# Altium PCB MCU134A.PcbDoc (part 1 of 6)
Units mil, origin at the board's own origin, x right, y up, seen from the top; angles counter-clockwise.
Board outline 4163.98 x 2693.8 mil, 6 copper layers (Top Layer, GND1, SIG1, PWR, GND2, Bottom), stack 58.132 mil thick; 218 components, 287 nets, 1260 pads, 770 vias.
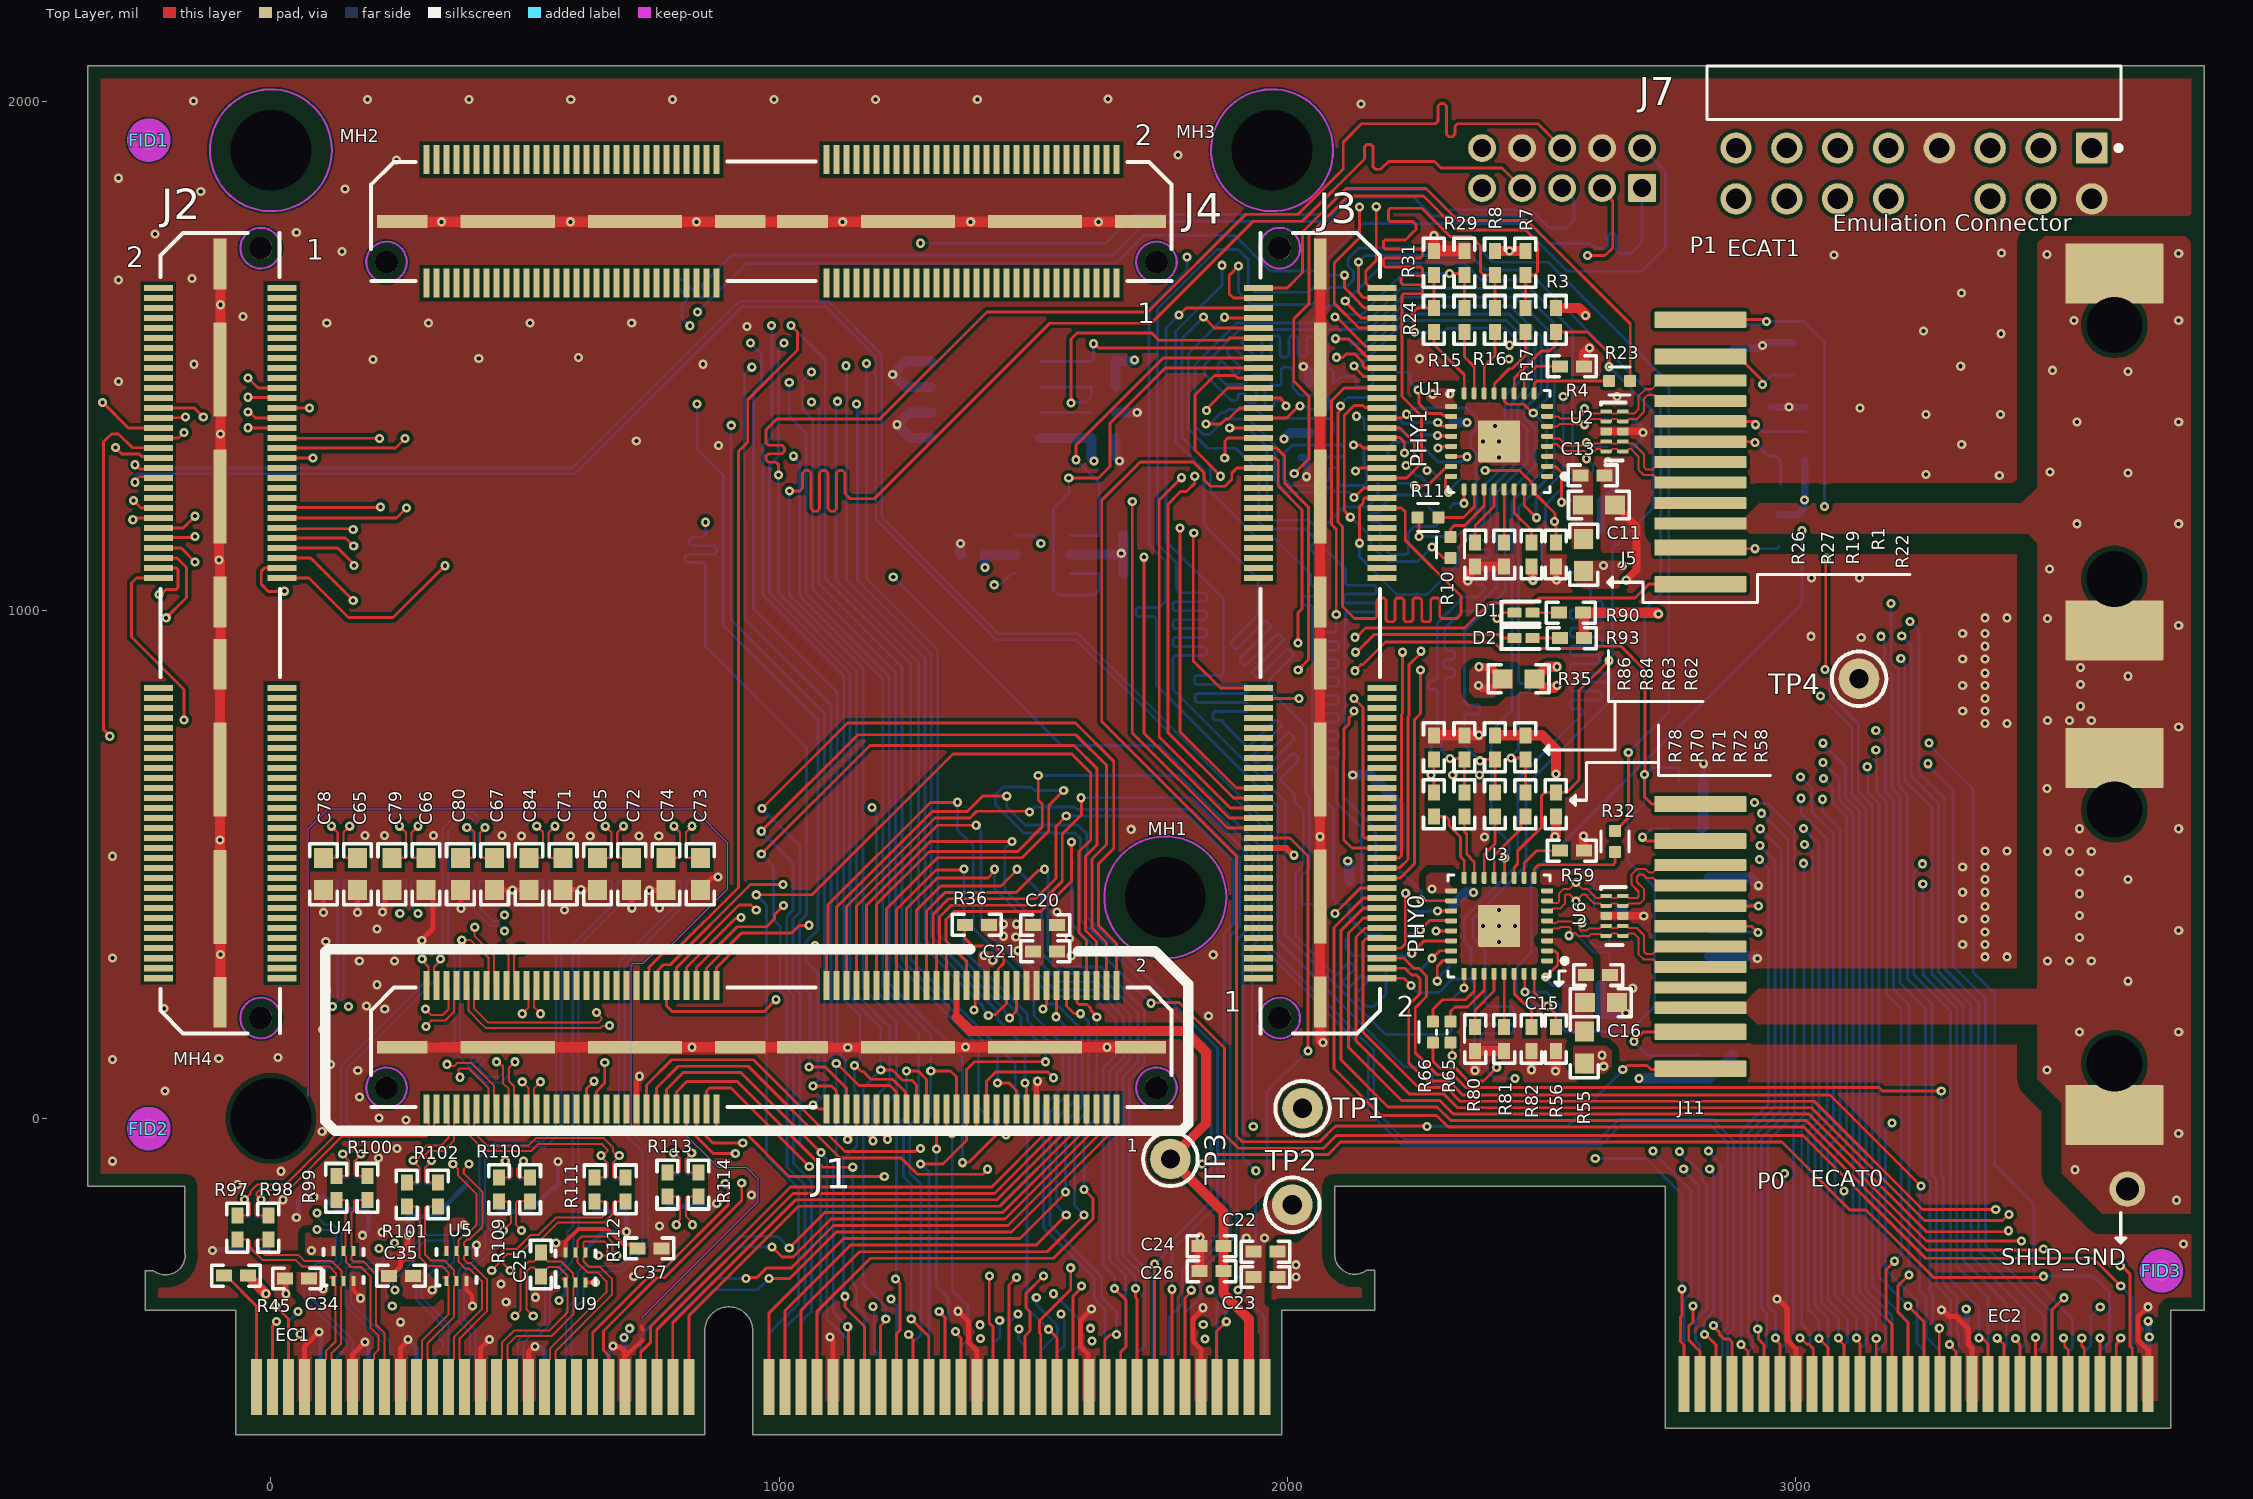
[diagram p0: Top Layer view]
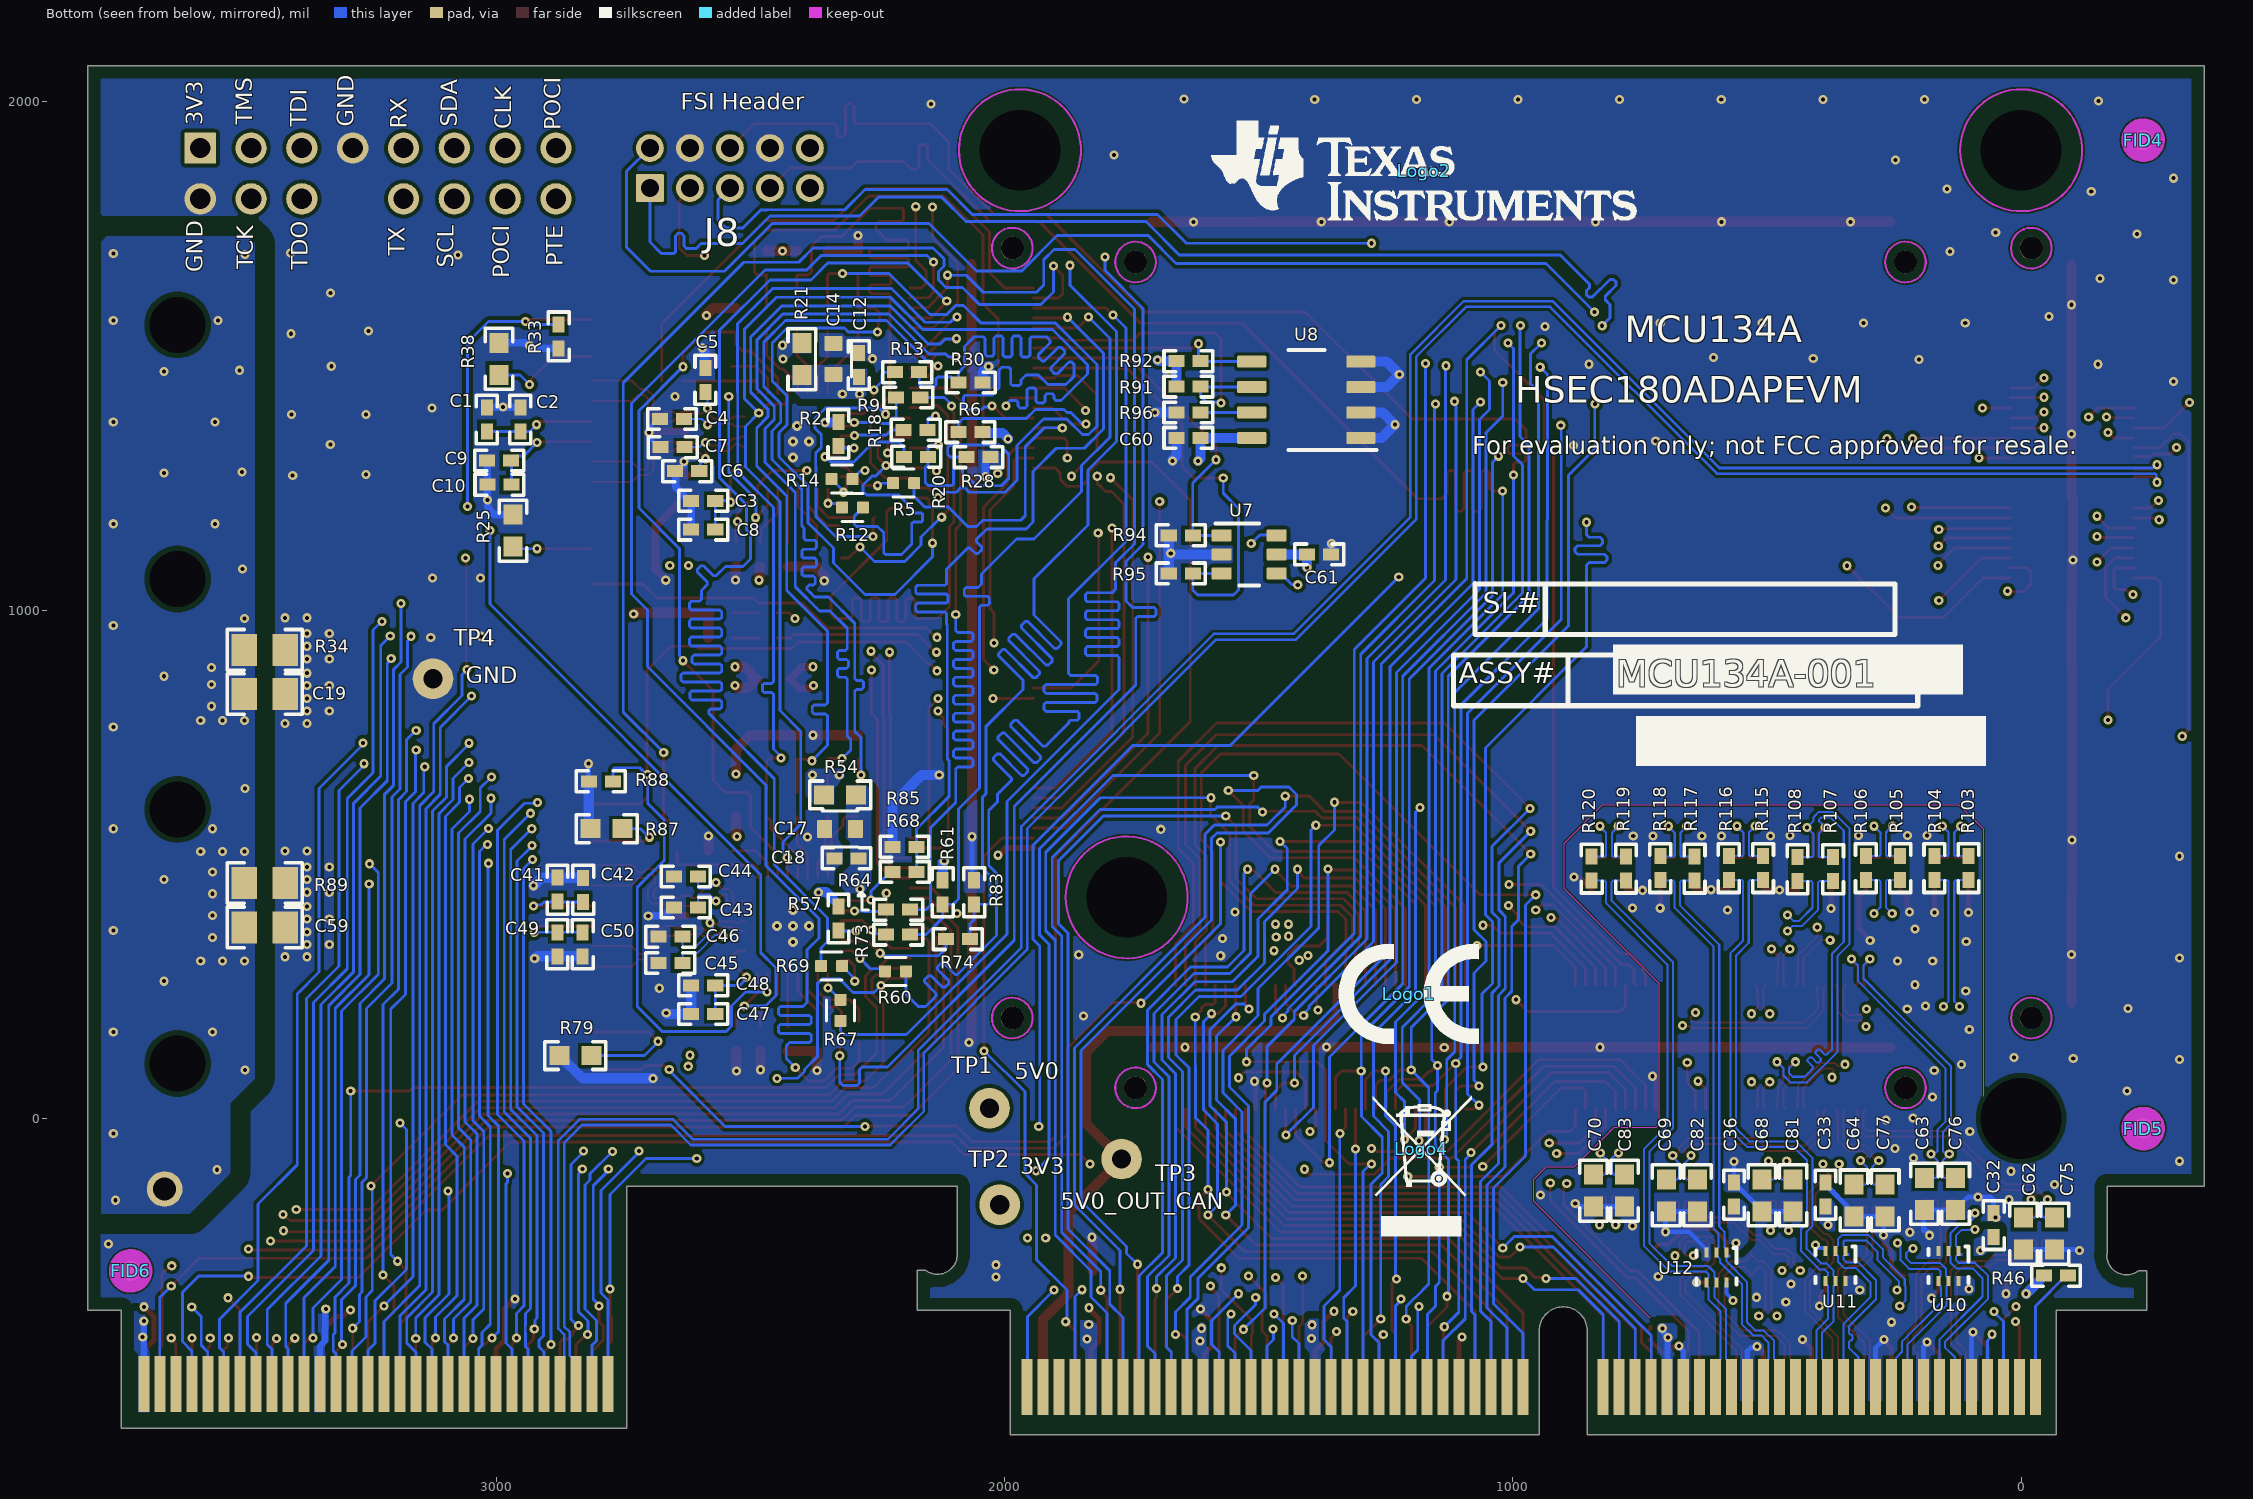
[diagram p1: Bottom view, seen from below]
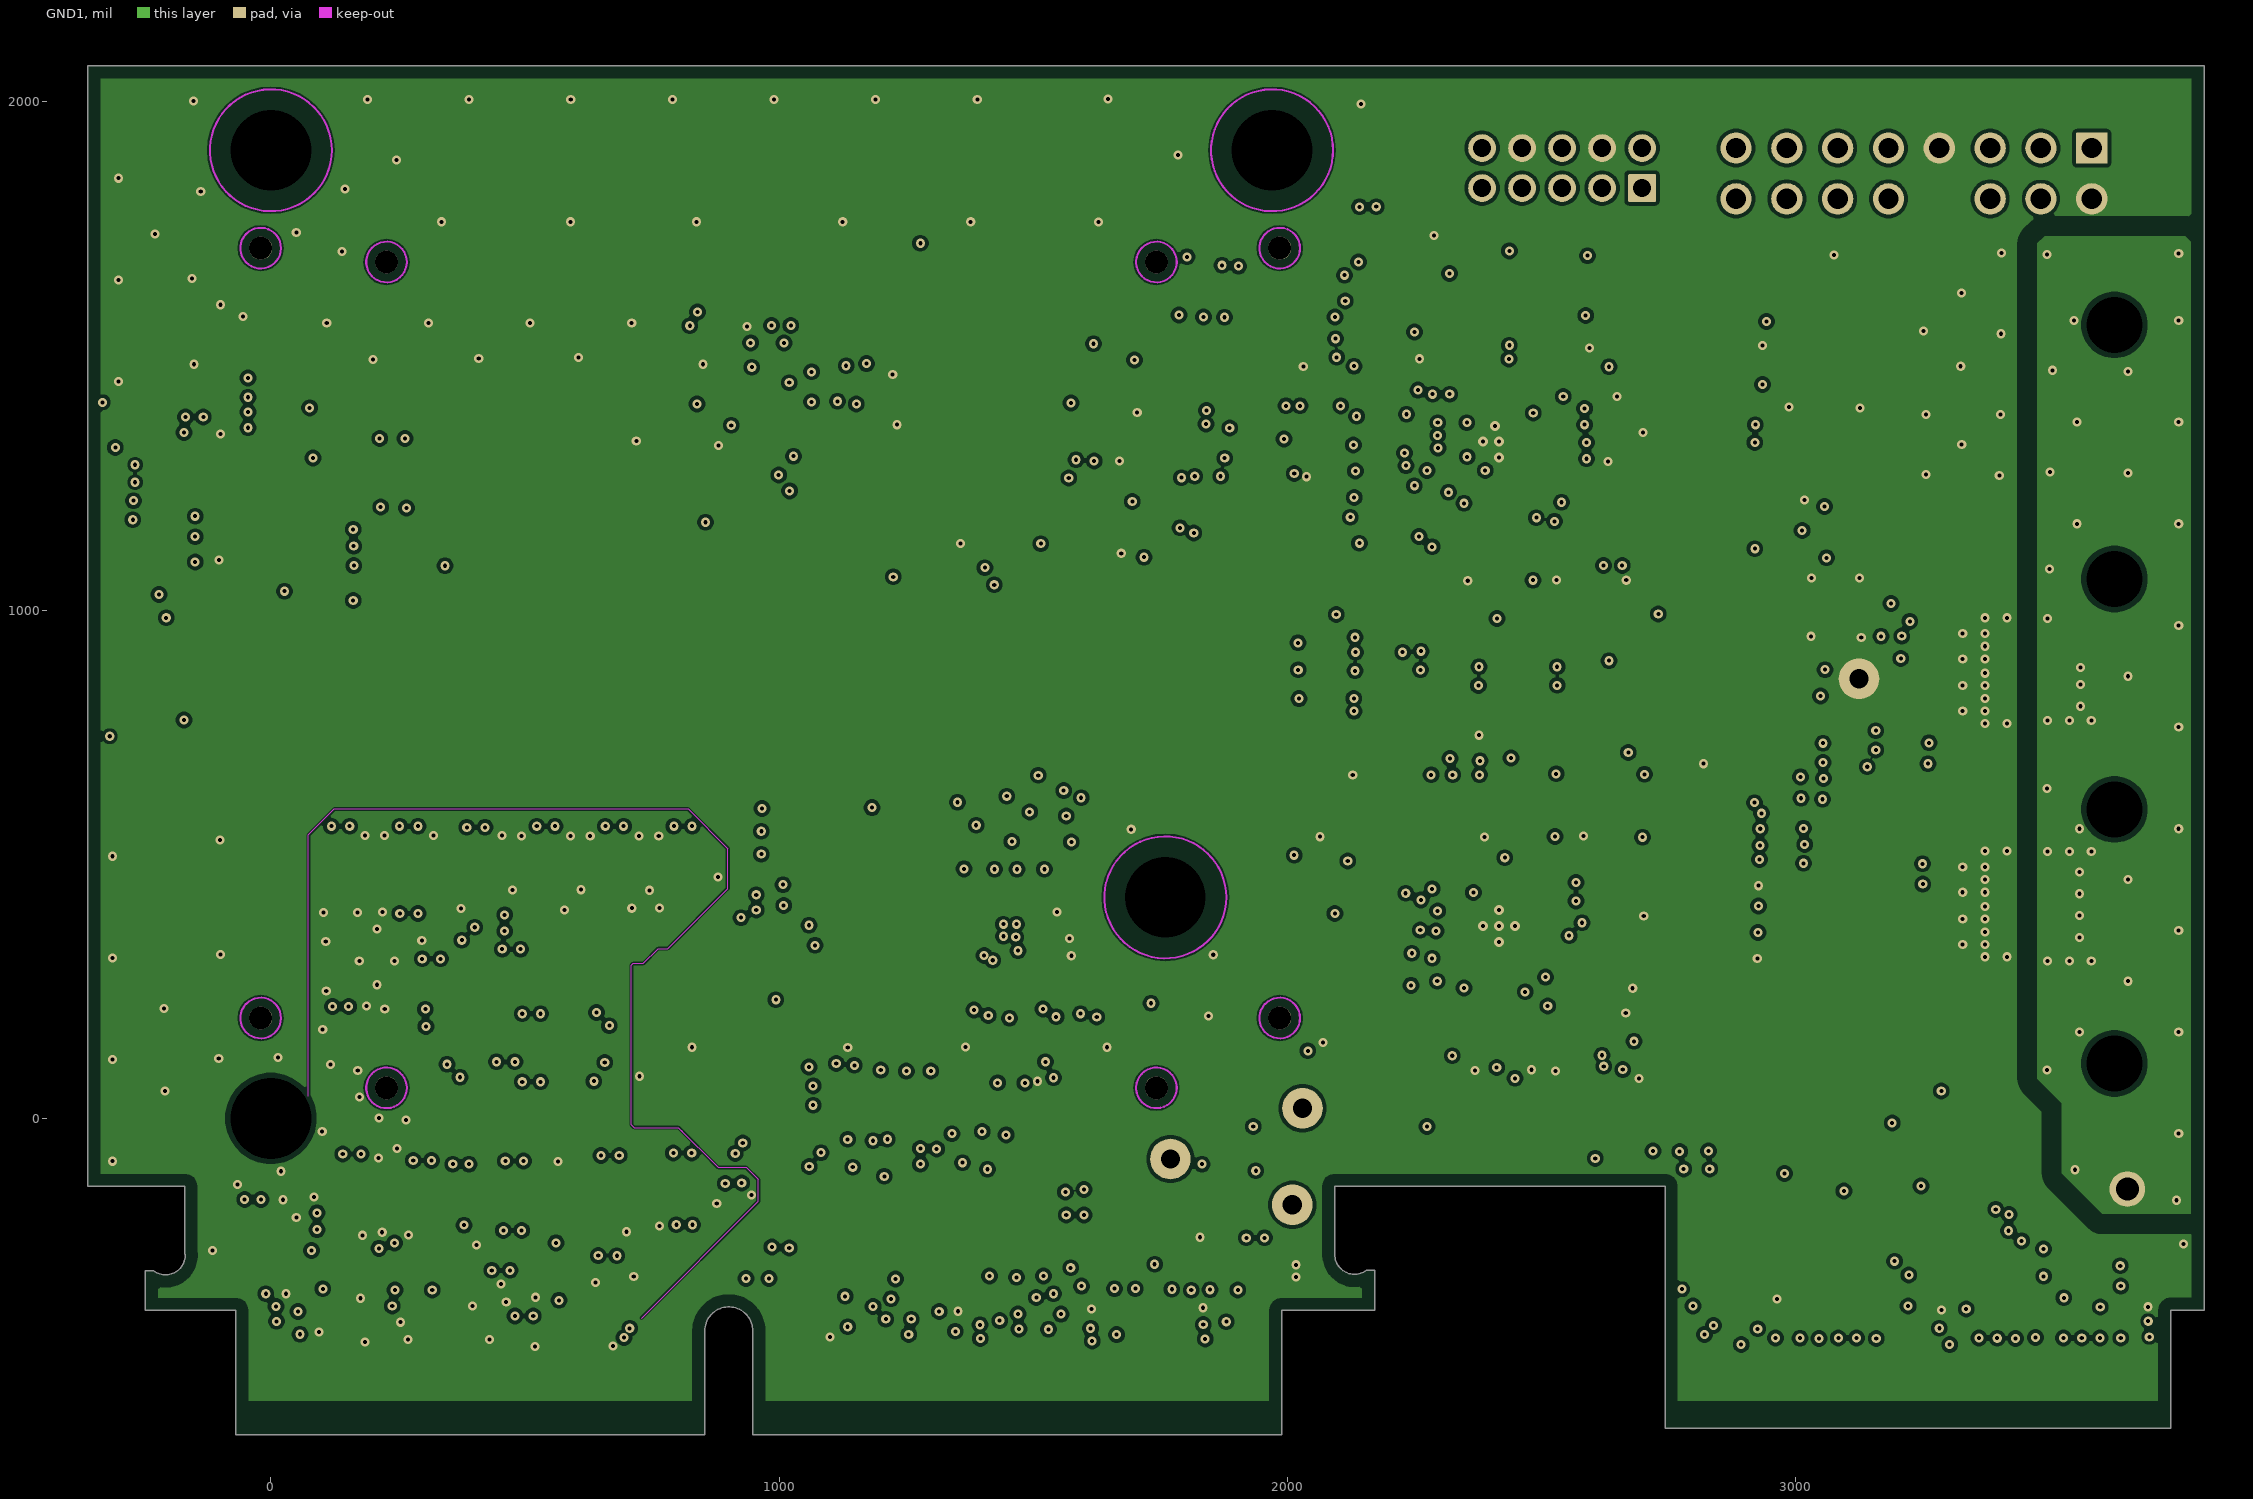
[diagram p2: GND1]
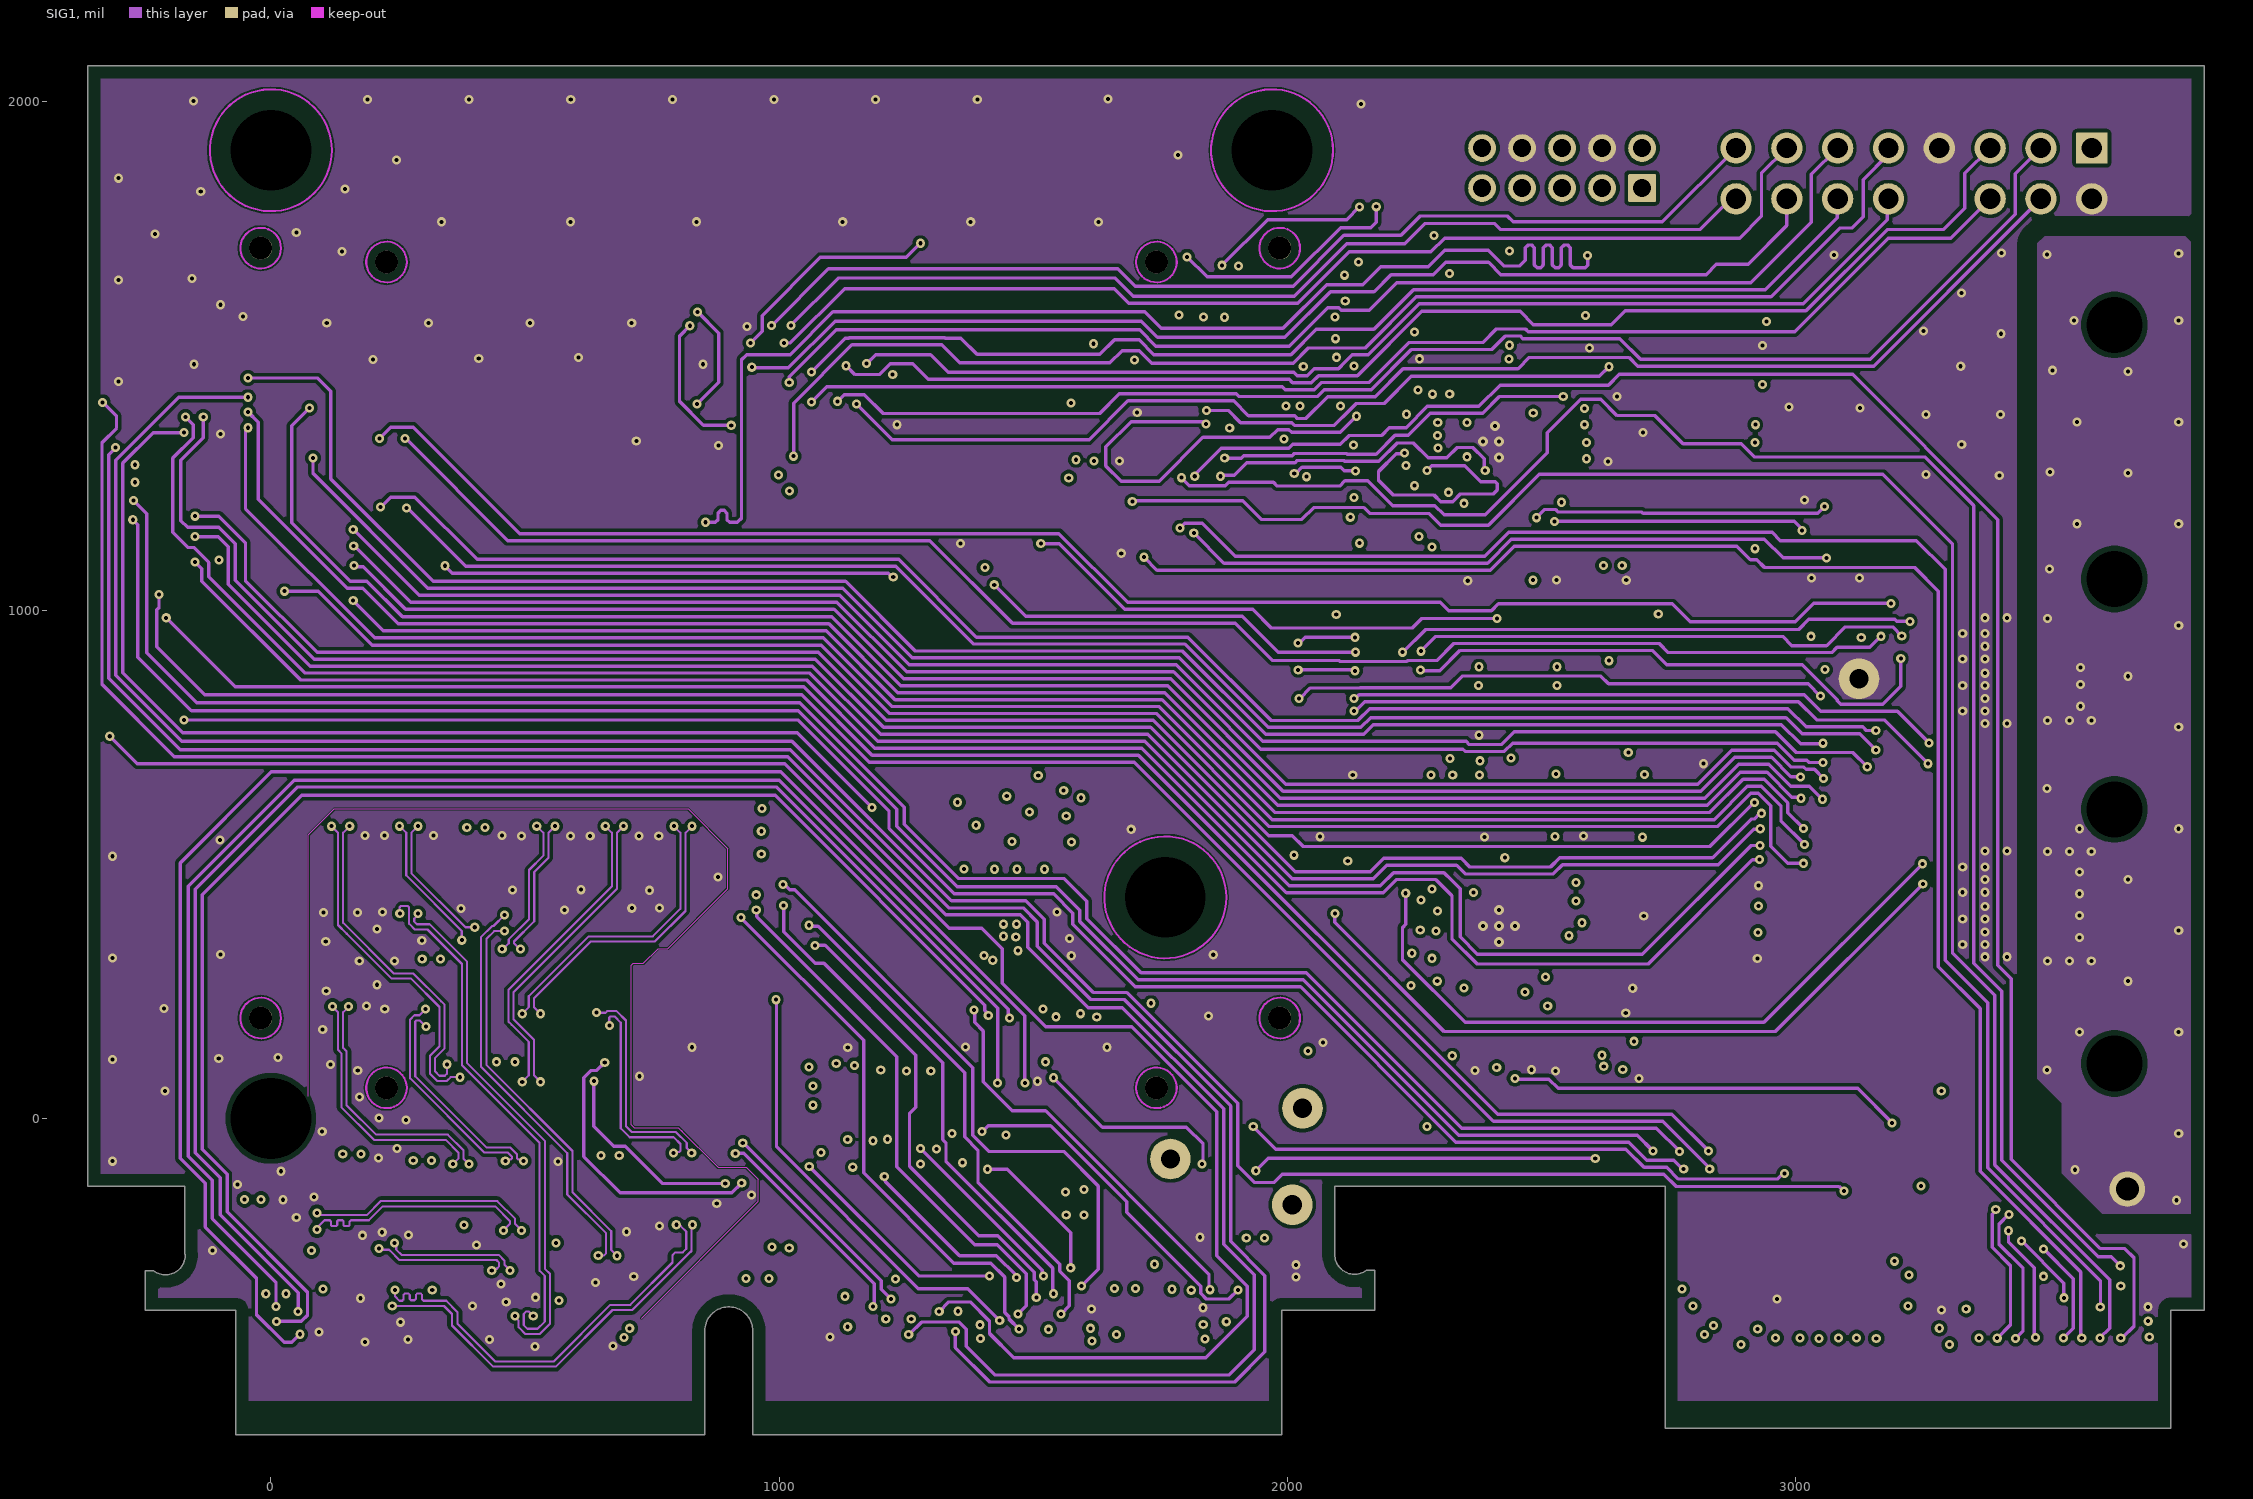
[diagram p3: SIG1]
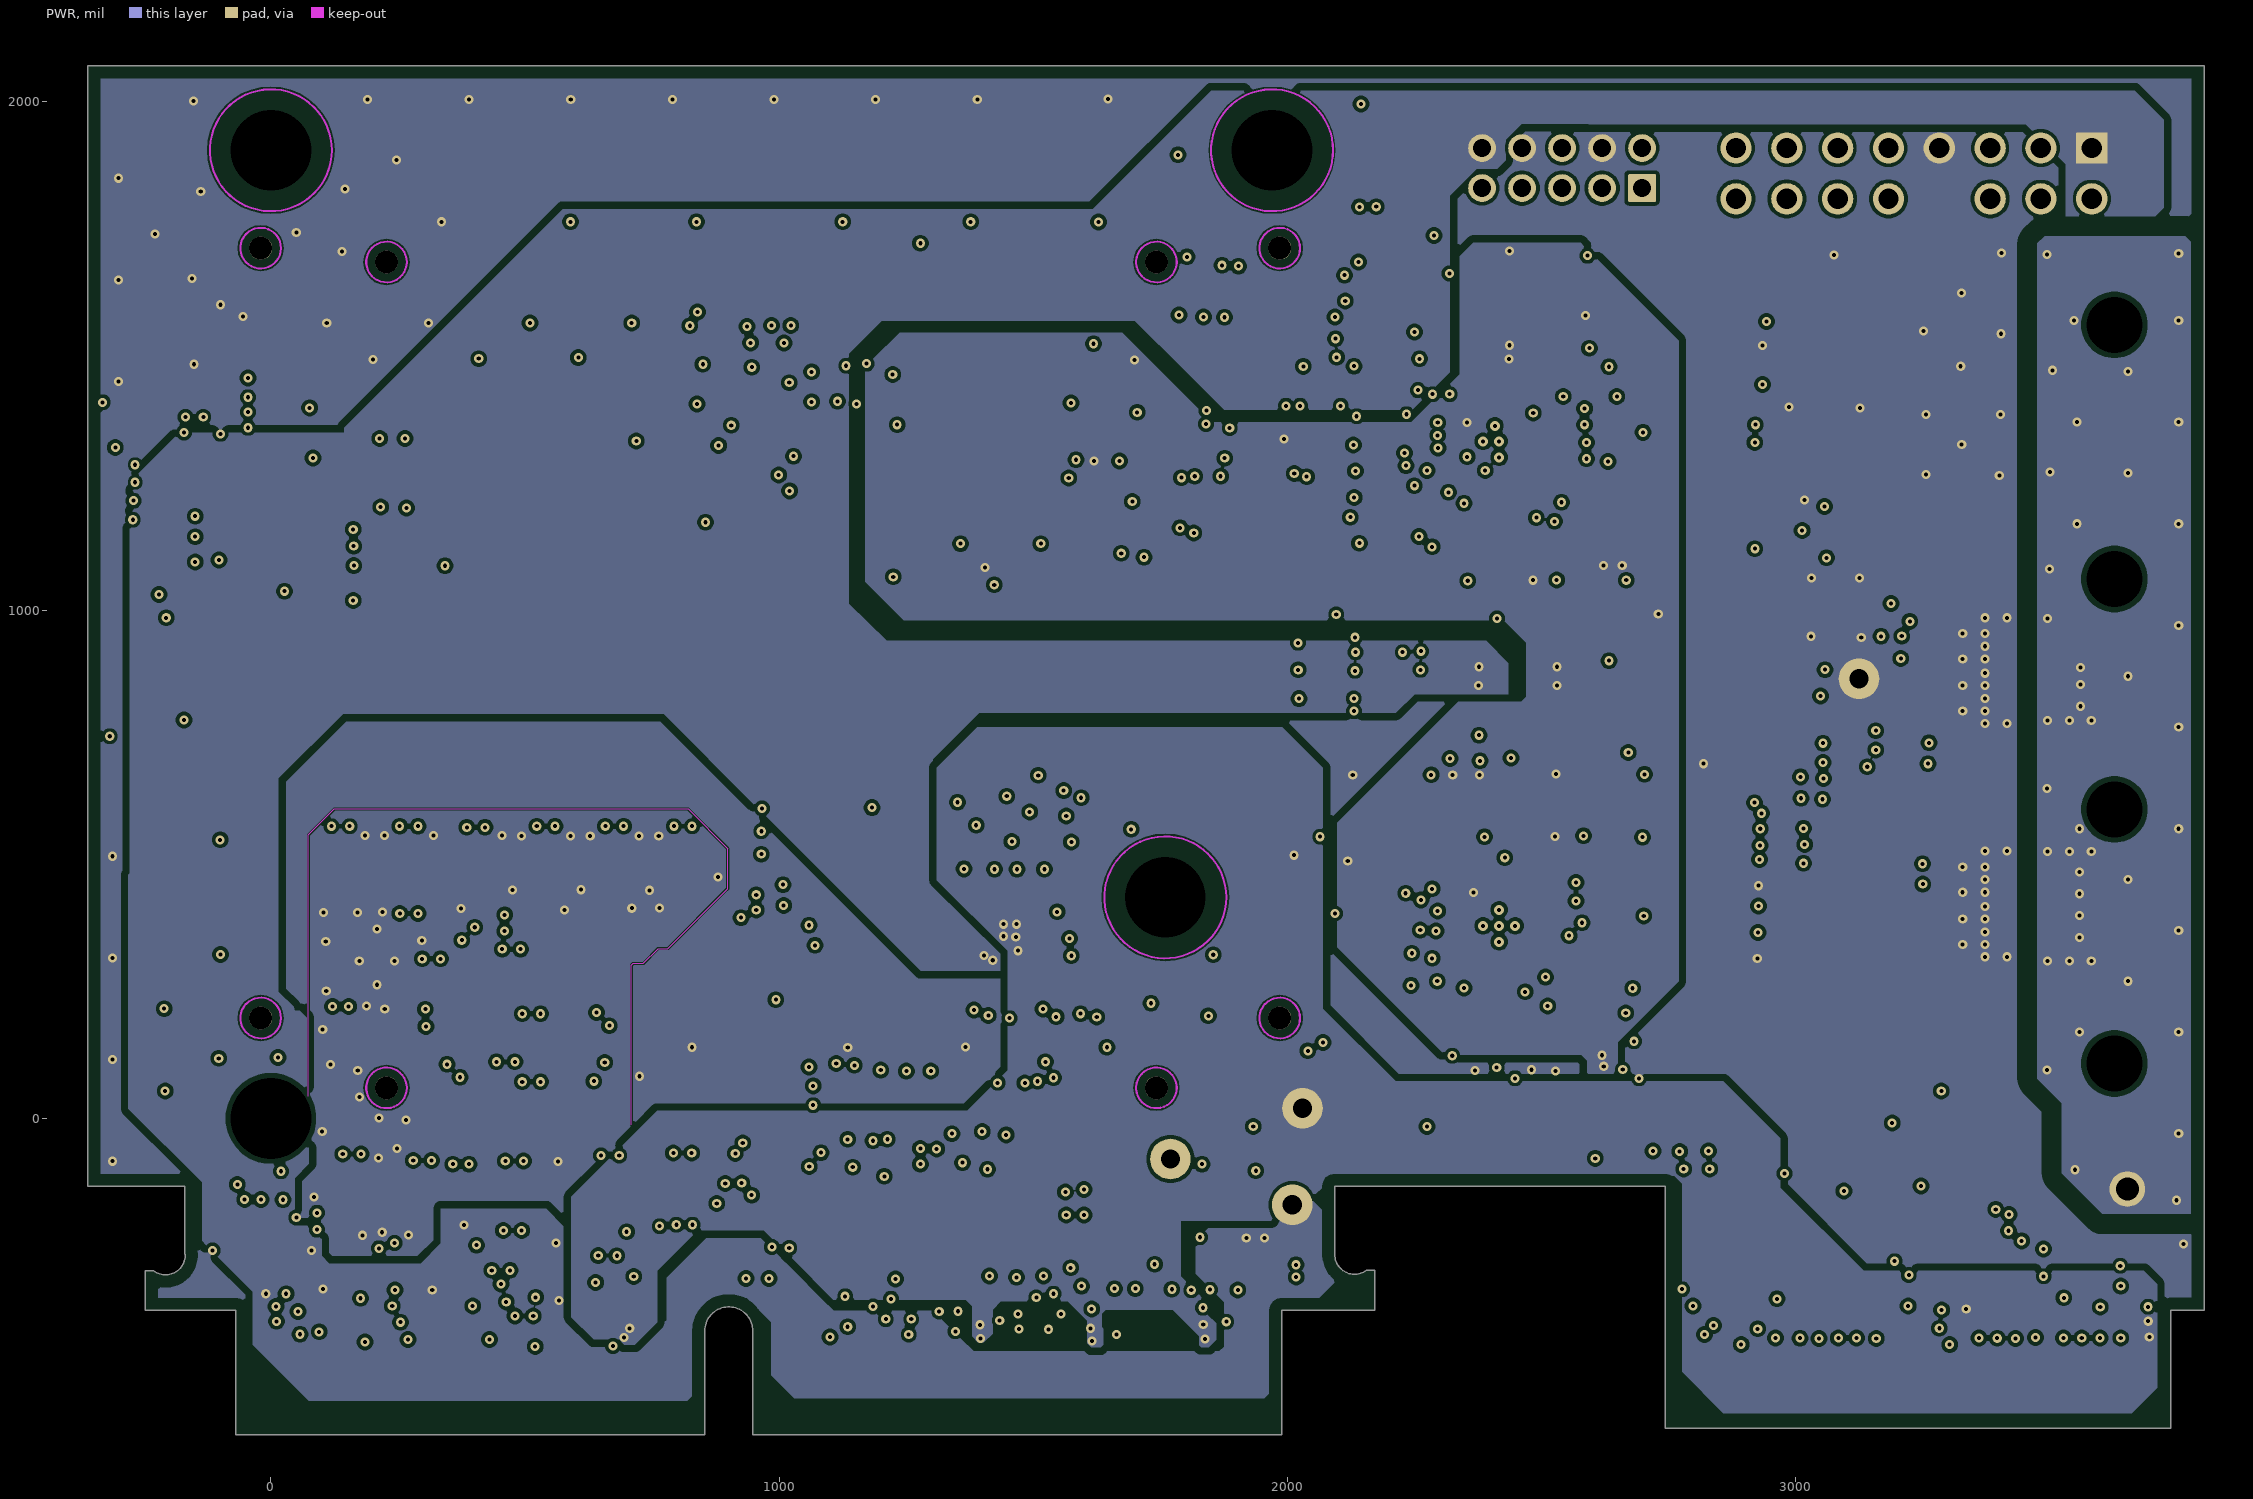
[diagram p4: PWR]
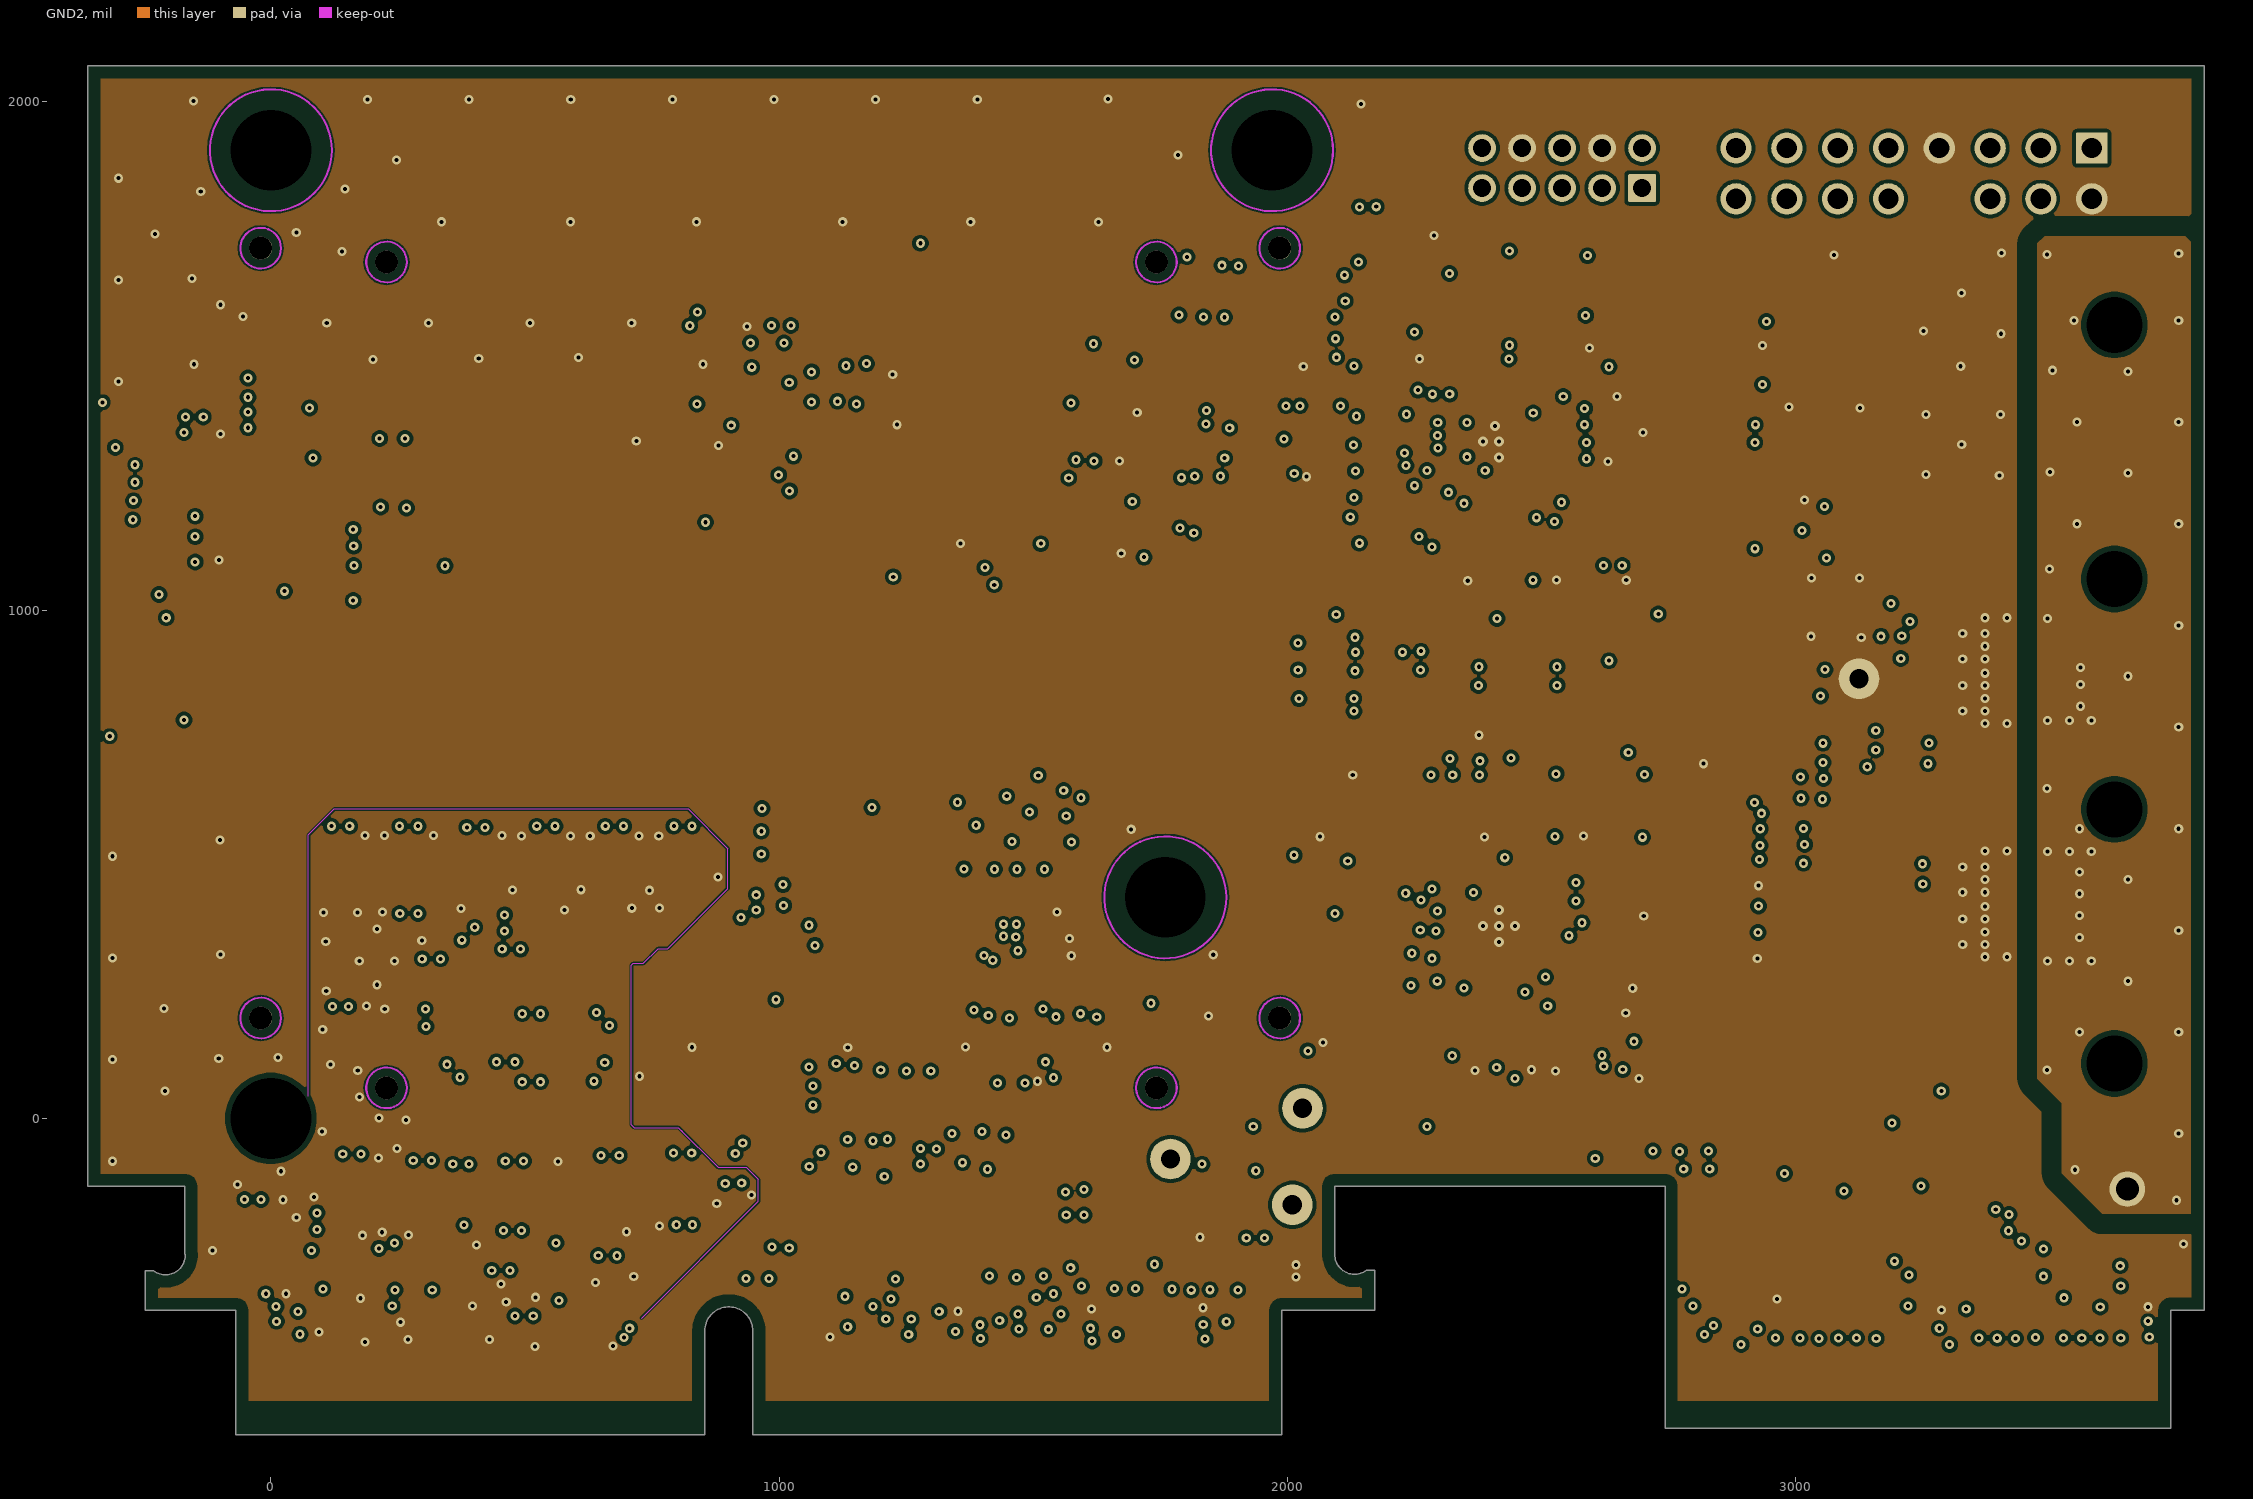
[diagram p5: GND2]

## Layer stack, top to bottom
Top Solder: solder mask 2, Solder Resist, Dk 3.6
Top Layer: signal copper 1.85
Dielectric 1: prepreg 3.696, FR-4, Dk 4.1
GND1: signal copper 1.26
Dielectric 2: core 5, FR-4, Dk 3.7
SIG1: signal copper 1.26
Dielectric 3: prepreg 32, FR-4, Dk 3.7
PWR: signal copper 1.26
Dielectric 4: core 5, FR-4, Dk 3.7
GND2: signal copper 1.26
Dielectric 5: prepreg 3.696, FR-4, Dk 4.1
Bottom: signal copper 1.85
Bottom Solder: solder mask 2, Solder Resist, Dk 3.6

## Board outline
-68.64,-622.81 853.8,-622.81 853.8,-418.09 cw(c901.05,-418.09) 948.29,-418.09 948.29,-622.81 1989.23,-622.81 1989.23,-377.97 2171.95,-377.97 2171.95,-298.97 2155.95,-298.97 cw(c2132.45,-267.85) 2093.45,-267.97 2092.95,-267.97 2092.95,-133.97 2743.26,-133.97 2743.26,-609.97 3738.54,-609.97 3738.54,-377.87 3803.95,-377.87 3803.95,2070.99 1606.27,2070.99 -360.03,2070.98 -360.03,-133.97 -169.05,-133.97 -169.05,-266.97 -168.55,-266.95 cw(c-207.5,-268.88) -231.05,-299.97 -247.05,-299.97 -247.05,-377.97 -68.64,-377.97

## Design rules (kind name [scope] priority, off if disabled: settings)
AcuteAngle [All] p1: minimum=4.50000000000000E+0001 checktracksonly=FALSE
AssemblyTestPointUsage [All] p1: valid=2
BoardOutlineClearance "Edge exception" [OnCopper and Not InComponentClass('Logo') and not InComponentClass('FiducialMark') and not InRegion(1000,500,4000,800) and not InPoly and ((Name = 'EC2') or (Name = 'EC1'))] p1: gap=0 ignorepadtopadclearanceinfootprint=FALSE
BoardOutlineClearance BoardOutlineClearance_MountingHoles [OnCopper and InComponentClass('Mounting Holes')] p2: gap=40 ignorepadtopadclearanceinfootprint=FALSE
BoardOutlineClearance BoardOutlineClearance_Poly [OnCopper and IsPoly] p3: gap=25 ignorepadtopadclearanceinfootprint=FALSE
Clearance HSEC_CON [InDifferentialPairClass('HSEC')OR InDifferentialPairClass('CON1')] p1: gap=7 ignorepadtopadclearanceinfootprint=TRUE except(6: Arc-Arc Arc-Track Arc-Via Track-Track Track-Via; 10: Arc-Hole Track-Hole SMDPad-Hole THPad-Hole Via-Hole Fill-Hole Poly-Hole Region-Hole Text-Hole; 14: Via-Via; 15: Fill-Fill Fill-Poly Fill-Region Poly-Poly Region-Region)
Clearance Clearance__shieldground [InNet('SHLD_GND') vs InNet('GND')] p2: gap=6 ignorepadtopadclearanceinfootprint=FALSE except(8: Region-Hole Text-Text Text-Hole; 40: Poly-Poly)
Clearance clearance_keepouttrace [KeepoutRestrictionsTrack] p3: gap=3 ignorepadtopadclearanceinfootprint=FALSE except(0: Arc-Arc Arc-Track Arc-SMDPad Track-Track Track-SMDPad; 7: Poly-Region)
Clearance Clearance_FiducialMark [IsKeepOut and InComponentClass('FiducialMark') vs IsPad and InComponentClass('FiducialMark')] p4: gap=0 ignorepadtopadclearanceinfootprint=TRUE
Clearance DIFF_90E [InDifferentialPairClass('DIFF_90E')] p5: gap=6 ignorepadtopadclearanceinfootprint=TRUE except(0: Arc-Text Arc-Hole Track-Text Track-Hole SMDPad-Via SMDPad-Text SMDPad-Hole THPad-Text THPad-Hole Via-Text Via-Hole Fill-Text Fill-Hole Poly-Text Poly-Hole Region-Text Region-Hole Text-Text Text-Hole; 6.22: Arc-Arc Arc-Track Track-Track; 7: Poly-Region; 12.44: Via-Via; 15: Fill-Fill Fill-Poly Fill-Region Poly-Poly Region-Region)
Clearance ESC_ETHER [InNetClass('ESC_RX0_ETHER') or InNetClass('ESC_RX1_ETHER') or InNetClass('ESC_TX0_ETHER') or InNetClass('ESC_TX1_ETHER') or InNetClass('FSIRX') or InNetClass('FSITX') or InNetClass('ESC_MDIO') vs OnTopLayer or OnBottomLayer] p6: gap=7 ignorepadtopadclearanceinfootprint=FALSE except(6: Arc-SMDPad Arc-Via Track-SMDPad Track-Via; 10: Arc-Hole Track-Hole SMDPad-Hole THPad-Hole Via-Hole Fill-Hole Poly-Hole Region-Hole Text-Hole; 15: Fill-Fill Fill-Poly Fill-Region Poly-Poly Region-Region)
Clearance [All] p7: gap=7 ignorepadtopadclearanceinfootprint=TRUE except(6: Arc-SMDPad Arc-Via Track-SMDPad Track-Via; 10: Arc-Hole Track-Hole SMDPad-Hole THPad-Hole Via-Hole Fill-Hole Poly-Hole Region-Hole Text-Hole; 15: Fill-Fill Fill-Poly Fill-Region Poly-Poly Region-Region)
Clearance Clearance_Keepouts [((IsTrack Or IsArc) And Not InPoly) And IsFree and IsKeepOut vs ((IsTrack Or IsArc) And Not InPoly) And IsFree and IsKeepOut] p8: gap=0 ignorepadtopadclearanceinfootprint=FALSE
Clearance Clearance_Poly [InPolygon] p9: gap=8 ignorepadtopadclearanceinfootprint=FALSE except(7: Poly-Region; 15: Fill-Fill Fill-Poly Fill-Region Poly-Poly Region-Region)
ComponentClearance ComponentClearance_MountingHoles_FiducialMarks [InComponentClass('Mounting Holes') vs InComponentClass('FiducialMark')] p1: gap=50 collisioncheckmode=3 verticalgap=10 showdistances=FALSE
ComponentClearance ComponentClearance_Shunt [InComponentClass('Header') vs InComponentClass('Shunt')] p2: gap=0 collisioncheckmode=3 verticalgap=0 showdistances=FALSE
ComponentClearance ComponentClearance_Logo [InComponentClass('Logo')] p3: gap=50 collisioncheckmode=3 verticalgap=10 showdistances=FALSE
ComponentClearance ComponentClearance_ScrewToNut [(HasFootprint('NY PMS 440 0025 PH')) vs (HasFootprint('Keystone_1902C'))] p4: gap=5 collisioncheckmode=3 verticalgap=10 showdistances=FALSE
ComponentClearance ComponentClearance_MountingHoles [InComponentClass('Mounting Holes')] p5: gap=250 collisioncheckmode=3 verticalgap=100000 showdistances=FALSE
ComponentClearance ComponentClearance_SmallPassives [HasFootprint('0201*') or HasFootprint('0402*') or HasFootprint('0508') or HasFootprint('0603*') or HasFootprint('0612') or HasFootprint('0805*') or HasFootprint('0815*') or HasFootprint('0830*') or HasFootprint('1206*') or HasFootprint('1210*') or HasFootprint('1808*') or HasFootprint('1812*') or HasFootprint('1825*') or HasFootprint('2010*') or HasFootprint('2220*') or HasFootprint('2225*') or HasFootprint('2512*') or HasFootprint('2728*') or HasFootprint('3518*') vs HasFootprint('0201*') or HasFootprint('0402*') or HasFootprint('0508') or HasFootprint('0603*') or HasFootprint('0612') or HasFootprint('0805*') or HasFootprint('0815*') or HasFootprint('0830*') or HasFootprint('1206*') or HasFootprint('1210*') or HasFootprint('1808*') or HasFootprint('1812*') or HasFootprint('1825*') or HasFootprint('2010*') or HasFootprint('2220*') or HasFootprint('2225*') or HasFootprint('2512*') or HasFootprint('2728*') or HasFootprint('3518*')] p6: gap=14.96 collisioncheckmode=3 verticalgap=10 showdistances=FALSE
ComponentClearance ComponentClearance_THtoSMT [IsThruComponent vs IsSMTComponent] p7: gap=10 collisioncheckmode=3 verticalgap=10 showdistances=FALSE
ComponentClearance "ComponentClearance_TP to TP" [(INComponent('TP1:A') or InComponent('TP2:A') or InComponent('TP3:A')or InComponent('TP7') or InComponent('TP2') or InComponent('TP3') or InComponent('TP10')) vs (INComponent('TP1:A') or InComponent('TP2:A') or InComponent('TP3:A')or InComponent('TP7') or InComponent('TP2') or InComponent('TP3') or InComponent('TP10'))] p8: gap=20 collisioncheckmode=3 verticalgap=30 showdistances=FALSE
ComponentClearance ComponentClearance_THtoTH [IsThruComponent vs IsThruComponent] p9: gap=30 collisioncheckmode=3 verticalgap=30 showdistances=FALSE
ComponentClearance [All] p10: gap=10 collisioncheckmode=3 verticalgap=10 showdistances=FALSE
DiffPairsRouting DiffPairsRouting_100OHM [InDifferentialPairClass('CON1')or InDifferentialPairClass('HSEC')] p1: maxlimit=10 minlimit=6 mostfreqgap=10 toplayer_mingap=7 toplayer_maxgap=7 toplayer_prefgap=7 toplayer_minwidth=4 toplayer_maxwidth=4 toplayer_prefwidth=4 midlayer1_maxgap=6 midlayer1_prefgap=6 midlayer1_minwidth=4.2 midlayer1_maxwidth=4.2 midlayer1_prefwidth=4.2 midlayer2_mingap=10 midlayer2_minwidth=15 midlayer2_maxwidth=15 midlayer2_prefwidth=15 midlayer3_mingap=10 midlayer3_minwidth=15 midlayer3_maxwidth=15 midlayer3_prefwidth=15 midlayer4_maxgap=6 midlayer4_prefgap=6 midlayer4_minwidth=4.2 midlayer4_maxwidth=4.2 midlayer4_prefwidth=4.2 bottomlayer_mingap=7 bottomlayer_maxgap=7 bottomlayer_prefgap=7 bottomlayer_minwidth=4 bottomlayer_maxwidth=4 bottomlayer_prefwidth=4 maxuncoupledlength=600
DiffPairsRouting DiffPairsRouting_90OHM [InDifferentialPairClass('DIFF_90E')] p2: maxlimit=10 minlimit=6 mostfreqgap=10 toplayer_mingap=6.22 toplayer_maxgap=6.22 toplayer_prefgap=6.22 toplayer_minwidth=5 toplayer_maxwidth=5 toplayer_prefwidth=5 midlayer1_maxgap=6 midlayer1_prefgap=6 midlayer1_minwidth=5.7 midlayer1_maxwidth=5.7 midlayer1_prefwidth=5.7 midlayer2_mingap=10 midlayer2_minwidth=15 midlayer2_maxwidth=15 midlayer2_prefwidth=15 midlayer3_mingap=10 midlayer3_minwidth=15 midlayer3_maxwidth=15 midlayer3_prefwidth=15 midlayer4_maxgap=6 midlayer4_prefgap=6 midlayer4_minwidth=5.7 midlayer4_maxwidth=5.7 midlayer4_prefwidth=5.7 bottomlayer_mingap=6.22 bottomlayer_maxgap=6.22 bottomlayer_prefgap=6.22 bottomlayer_minwidth=5 bottomlayer_maxwidth=5 bottomlayer_prefwidth=5 maxuncoupledlength=500
FabricationTestPointUsage TestPointUsage [All] p1: valid=2 allowmultiple=FALSE
FabricationTestpoint Testpoint [All] p1: side=3 testpointundercomponent=TRUE minsize=40 maxsize=100 preferedsize=60 minholesize=0 maxholesize=40 preferedholesize=32 testpointgrid=1 allowsidetop=TRUE allowsidebottom=TRUE usegrid=TRUE gridtolerance=0.01
FanoutControl Fanout_LCC [IsLCC] p1: bgadir=Out bgaviamode=Centered fanoutstyle=Auto fanoutdirection=Alternating viagrid=1 // Fanout_LCC (Default Rule)
FanoutControl Fanout_BGA [IsBGA] p2: bgadir=Out bgaviamode=Centered fanoutstyle=Auto fanoutdirection=Alternating viagrid=1 // Fanout_BGA (Default Rule)
FanoutControl Fanout_Default [All] p4: bgadir=Out bgaviamode=Centered fanoutstyle=Auto fanoutdirection=Alternating viagrid=1 // Fanout_Default (Default Rule)
FanoutControl Fanout_Small [(CompPinCount < 5)] p5: bgadir=Out bgaviamode=Centered fanoutstyle=Auto fanoutdirection=OutThenIn viagrid=1 // Fanout_Small (Default Rule)
HoleSize [All] p1: absolutevalues=TRUE maxlimit=251 minlimit=7.87 maxpercent=80.000 minpercent=20.000
HoleToHoleClearance [All] p1: gap=9 allowstackedmicrovias=TRUE
MatchedLengths ESC_TX0_ETHER [InxSignalClass('ESC_TX0_ETHER')] p1: tolerance=15 checknetsindiffpair=FALSE checkdiffpairvsdiffpair=TRUE checkxsignals=TRUE checkothers=TRUE targetsourcename=ESC_TX0_CLK-NetR74_2_PP1
MatchedLengths ESC_TX1_ETHER [InxSignalClass('ESC_TX1_ETHER')] p2: tolerance=15 checknetsindiffpair=FALSE checkdiffpairvsdiffpair=TRUE checkxsignals=TRUE checkothers=TRUE targetsourcename=ESC_TX1_CLK-NetR20_2_PP1
MatchedLengths CON1 [InDifferentialPairClass('CON1')] p3: tolerance=5 checknetsindiffpair=TRUE checkdiffpairvsdiffpair=FALSE checkxsignals=FALSE checkothers=FALSE
MatchedLengths FSITX [InxSignalClass('FSI_TX SIGNALS')] p4: tolerance=20 checknetsindiffpair=FALSE checkdiffpairvsdiffpair=TRUE checkxsignals=TRUE checkothers=TRUE targetsourcename=FSITX_CLK-NetJ8_7_PP1
MatchedLengths FSIRX [InxSignalClass('FSI_RX SIGNALS')] p5: tolerance=20 checknetsindiffpair=FALSE checkdiffpairvsdiffpair=TRUE checkxsignals=TRUE checkothers=TRUE targetsourcename=FSIRX_CLK-NetJ8_3_PP1
MatchedLengths HSEC [InDifferentialPairClass('HSEC')] p6: tolerance=5 checknetsindiffpair=TRUE checkdiffpairvsdiffpair=FALSE checkxsignals=FALSE checkothers=FALSE
MinimumAnnularRing [All] p1: minimumring=5
MinimumSolderMaskSliver MinimumSolderMaskSliver_Logo [InComponentClass('Logo') vs InComponentClass('MCU134E1_High_Density_connector1_and_2')] p1: minsoldermaskwidth=0.7
MinimumSolderMaskSliver [All] p2: minsoldermaskwidth=3
PlaneClearance [All] p1: clearance=10
PlaneConnect [All] p1: planeconnectstyle=Direct reliefexpansion=10 reliefentries=4 reliefconductorwidth=10 reliefairgap=10
PolygonConnect [All] p1: connectstyle=Direct reliefconductorwidth=10 reliefentries=4 polygonreliefangle="90 Angle" airgapwidth=10
RoutingVias [All] p1: holewidth=8 width=22 viastyle="Through Hole" minholewidth=7.87 minwidth=18 maxholewidth=8 maxwidth=22
ShortCircuit [InComponentClass(('MCU134E1_EtherCAT_PHY_1')AND ('MCU134E1_EtherCAT_PHY_1'))] p1: allowed=TRUE
SilkToBoardRegionClearance [Not ((IsComment or IsDesignator) And (Hide <> 'False')) and not InRegion(1000,500,4000,800)] p1:
SilkToSilkClearance SilkToSilkClearance_Pb-FreeLogo [(HasFootprint('Pb-Free_Overlay_Medium') OR HasFootprint('Pb-Free_Overlay_Small')) vs (HasFootprint('Pb-Free_Overlay_Medium') OR HasFootprint('Pb-Free_Overlay_Small'))] p1: silktosilkclearance=1
SilkToSilkClearance [All] p2: silktosilkclearance=3
SilkToSolderMaskClearance [(HasFootprint('FP-TSW-106-16-G-D-RA_HDR12-MFG')OR HasFootprint('FP-TSW-102-16-G-D-RA_HDR4-MFG') OR HasFootprint('FP-GRM188R60J476ME01D_0603-MFG')OR HasFootprint('0402')) vs HasFootprint('0402')] p1: minsilkscreentomaskgap=0 clearancetoexposedcopper=TRUE
SilkToSolderMaskClearance SilkToComponentPadClearance [(IsPad or IsFill or IsRegion) and InAnycomponent] p2: minsilkscreentomaskgap=0.3 clearancetoexposedcopper=TRUE
SilkToSolderMaskClearance "Silk to Solder Mask Opening" [all] p3: minsilkscreentomaskgap=0 clearancetoexposedcopper=FALSE
SolderMaskExpansion [All] p1: expansion=1.97 istentingtop=FALSE
UnRoutedNet [All] p1: checkbadconnections=TRUE
Width PWR_GND [InNetClass('PWR_GND')] p1: maxlimit=40 minlimit=8 preferedwidth=10 minimp=50.000000 maximp=50.000000 favimp=50.000000
Width [InNetClass('All Nets')] p2: maxlimit=40 minlimit=5.66 preferedwidth=6.66 toplayer_maxwidth=5.66 toplayer_prefwidth=5.66 midlayer1_minwidth=6.66 midlayer1_maxwidth=6.66 midlayer2_minwidth=10 midlayer2_prefwidth=20 midlayer3_minwidth=10 midlayer3_prefwidth=20 midlayer4_minwidth=6.66 midlayer4_maxwidth=6.66 bottomlayer_maxwidth=5.66 bottomlayer_prefwidth=5.66 minimp=50.000000 maximp=50.000000 favimp=50.000000 checkconnectedcopper=TRUE
11 further rules are at their usual default settings.

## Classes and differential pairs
differential pair class DIFF_90E: CON2_38_40
differential pair class PHY1: D_PHY1_RD D_PHY1_TD
differential pair class PHY0: D_PHY0_RD D_PHY0_TD
differential pair class CON1: CON1_97_99 CON1_98_100 CON1_102_104 CON1_103_101 CON1_105_107 CON1_106_108 CON1_109_111 CON1_110_112 CON1_114_116 CON1_115-113 CON1_117_119 CON1_118_120
differential pair class HSEC: HSEC1 HSEC2 HSEC3 HSEC4 HSEC5 HSEC6 HSEC7 HSEC8 HSEC9 HSEC10 HSEC11 HSEC12
net class 100E_con1: CON1_PIN105 CON1_PIN107
net class 90E: CON2_PIN38 CON2_PIN40
component class FiducialMark: FID1 FID2 FID3 FID4 FID5 FID6
net class ESC_MDIO: ESC_MDIO_CLK ESC_MDIO_DATA
net class FSITX: FSITX_CLK FSITX_D0 FSITX_D1
net class FSIRX: FSIRX_CLK FSIRX_D0 FSIRX_D1
net class ESC_TX1_ETHER: ESC_TX1_CLK ESC_TX1_DATA0 ESC_TX1_DATA1 ESC_TX1_DATA2 ESC_TX1_DATA3 ESC_TX1_ENA
net class ESC_TX0_ETHER: ESC_TX0_CLK ESC_TX0_DATA0 ESC_TX0_DATA1 ESC_TX0_DATA2 ESC_TX0_DATA3 ESC_TX0_ENA
net class ESC_RX1_ETHER: ESC_RX1_CLK ESC_RX1_DATA0 ESC_RX1_DATA1 ESC_RX1_DATA2 ESC_RX1_DATA3 ESC_RX1_DV ESC_RX1_ERR
net class ESC_RX0_ETHER: ESC_RX0_CLK ESC_RX0_DATA0 ESC_RX0_DATA1 ESC_RX0_DATA2 ESC_RX0_DATA3 ESC_RX0_DV ESC_RX0_ERR
net class HSEC_100ohm: HSEC_PIN9 HSEC_PIN11 HSEC_PIN12 HSEC_PIN14 HSEC_PIN15 HSEC_PIN17 HSEC_PIN18 HSEC_PIN20 HSEC_PIN21 HSEC_PIN23 HSEC_PIN24 HSEC_PIN25 HSEC_PIN26 HSEC_PIN27 HSEC_PIN28 HSEC_PIN30 HSEC_PIN31 HSEC_PIN33 HSEC_PIN34 HSEC_PIN36 HSEC_PIN37 HSEC_PIN39 HSEC_PIN40 HSEC_PIN42
net class PWR_GND: 3V3_ETH 3V3_OUT 5V0_IN 5V0_OUT_CAN GND SHLD_GND
component class MCU134E1_High_Density_connector3_and_4: J3 J4
component class MCU134E1_High_Density_connector1_and_2: J1 J2 J3 J4
component class "MCU134E1_FSI Header": J7 J8
component class MCU134E1_EtherCAT_PHY_1: C1 C2 C3 C4 C5 C6 C7 C8 C9 C10 C11 C12 C13 C14 C19 J5 R1 R2 R3 R4 R5 R6 R7 R8 R9 R10 R11 R12 R13 R14 R15 R16 R17 R18 R19 R20 R21 R22 R23 R24 R25 R26 R27 R28 R29 R30 R31 R33 R34 R38 U1 U2
component class MCU134E1_EtherCAT_PHY_0: C15 C16 C17 C18 C41 C42 C43 C44 C45 C46 C47 C48 C49 C50 C59 C60 C61 D1 D2 J11 R32 R54 R55 R56 R57 R58 R59 R60 R61 R62 R63 R64 R65 R66 R67 R68 R69 R70 R71 R72 R73 R74 R78 R79 R80 R81 R82 R83 R84 R85 R86 R87 R88 R89 R90 R91 R92 R93 R94 R95 R96 U3 U6 U7 U8
component class MCU134E1_ADC: , C25 C32 C33 C34 C35 C36 C37 C62 C63 C64 C65 C66 C67 C68 C69 C70 C71 C72 C73 C74 C75 C76 C77 C78 C79 C80 C81 C82 C84 C85 R103 R104 R105 R106 R107 R108 R111 R112 R113 R114 R115 R116 R117 R118 R119 R120 U4 U5 U9 U10 U11 U12
component class MCU134E1_180pin_Edge_Connector: C20 C21 C22 C23 C24 C26 EC1 EC2 R45 R46 TP1 TP2 TP3 TP4
component class MCU134E1_EVM_Hardware: FID1 FID2 FID3 FID4 FID5 FID6 Logo1 Logo2 Logo3 Logo4 MH1 MH2 MH3 MH4 ZZ1 ZZ2 ZZ3 ZZ4
differential pair CON2_38_40: +CON2_PIN38 -CON2_PIN40
differential pair CON1_110_112: +CON1_PIN112 -CON1_PIN110
differential pair CON1_98_100: +CON1_PIN100 -CON1_PIN98
differential pair CON1_97_99: +CON1_PIN99 -CON1_PIN97
differential pair CON1_115-113: +CON1_PIN115 -CON1_PIN113
differential pair CON1_102_104: +CON1_PIN104 -CON1_PIN102
differential pair CON1_103_101: +CON1_PIN103 -CON1_PIN101
differential pair CON1_106_108: +CON1_PIN108 -CON1_PIN106
differential pair CON1_114_116: +CON1_PIN116 -CON1_PIN114
differential pair CON1_118_120: +CON1_PIN120 -CON1_PIN118
differential pair CON1_105_107: +CON1_PIN107 -CON1_PIN105
differential pair CON1_109_111: +CON1_PIN111 -CON1_PIN109
differential pair CON1_117_119: +CON1_PIN119 -CON1_PIN117
differential pair HSEC12: +HSEC_PIN40 -HSEC_PIN42
differential pair HSEC11: +HSEC_PIN34 -HSEC_PIN36
differential pair HSEC10: +HSEC_PIN28 -HSEC_PIN30
differential pair HSEC9: +HSEC_PIN24 -HSEC_PIN26
differential pair HSEC8: +HSEC_PIN18 -HSEC_PIN20
differential pair HSEC7: +HSEC_PIN12 -HSEC_PIN14
differential pair HSEC6: +HSEC_PIN37 -HSEC_PIN39
differential pair HSEC5: +HSEC_PIN31 -HSEC_PIN33
differential pair HSEC4: +HSEC_PIN25 -HSEC_PIN27
differential pair HSEC3: +HSEC_PIN21 -HSEC_PIN23
differential pair HSEC2: +HSEC_PIN15 -HSEC_PIN17
differential pair HSEC1: +HSEC_PIN9 -HSEC_PIN11
differential pair D_PHY0_RD: +PHY0_RD_P -PHY0_RD_N
differential pair D_PHY0_TD: +PHY0_TD_P -PHY0_TD_N
differential pair D_PHY1_RD: +PHY1_RD_P -PHY1_RD_N
differential pair D_PHY1_TD: +PHY1_TD_P -PHY1_TD_N

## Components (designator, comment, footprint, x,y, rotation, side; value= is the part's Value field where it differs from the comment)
C1 "GRM155R71E104KE14D" 0402 3019,1375.38 r90 bottom value=0.1uF
C2 "GRM155R61E105KE11D" 0402 2953,1375.38 r90 bottom value=1uF
C3 "GRM155R71E104KE14D" 0402 2593.16,1215.17 r0 bottom value=0.1uF
C4 "GJM1555C1H4R7BB01D" 0402 2654.58,1376.25 r180 bottom value=4.7pF
C5 "GJM1555C1H4R7BB01D" 0402 2588.93,1453.4 r270 bottom value=4.7pF
C6 "GJM1555C1H4R7BB01D" 0402 2624.64,1273.43 r180 bottom value=4.7pF
C7 "GJM1555C1H4R7BB01D" 0402 2653.35,1320.83 r180 bottom value=4.7pF
C8 "GRM155R61E225ME15D" 0402 2593.16,1158.65 r0 bottom value=2.2uF
C9 "GRM155R71E104KE14D" 0402 2994.7,1294.63 r0 bottom value=0.1uF
C10 "GRM155R61E105KE11D" 0402 2994.28,1247 r0 bottom value=1uF
C11 "GRM188R61A226ME15D" 0603 2613.26,1206.95 r0 top value=22uF
C12 "GRM155R71E104KE14D" 0402 2287.1,1482.51 r90 bottom value=0.1uF
C13 "GRM155R71E104KE14D" 0402 2601.01,1265.25 r0 top value=0.1uF
C14 "GRM188R60J476ME01D" FP-GRM188R60J476ME01D_0603-MFG 2337.21,1494.51 r270 bottom value=47µF
C15 "GRM155R71E104KE14D" 0402 2611.62,282 r0 top value=0.1uF
C16 "GRM188R61A226ME15D" 0603 2616.88,227.66 r0 top value=22uF
C17 "GRM188R60J476ME01D" FP-GRM188R60J476ME01D_0603-MFG 2323.94,569.6 r180 bottom value=47µF
C18 "GRM155R71E104KE14D" 0402 2311.39,511.64 r0 bottom value=0.1uF
C19 "GRM2195C1H103JA01D" 0805_HV 3456,835 r180 bottom value=0.01uF
C20 "GRM155R61A106ME11D" 0402 1523.66,380.65 r0 top value=10uF
C21 "GRM155R71E104KE14D" 0402 1523.66,328.86 r0 top value=0.1uF
C22 "GRM155R61A106ME11D" 0402 1957.02,-262.37 r0 top value=10uF
C23 "GRM155R71E104KE14D" 0402 1957.02,-311.96 r0 top value=0.1uF
C24 "GRM155R61A106ME11D" 0402 1850.87,-251.43 r180 top value=10uF
C25 "GRM155R71E104KE14D" 0402 531.41,-287.47 r90 top value=0.1uF
C26 "GRM155R71E104KE14D" 0402 1850.87,-300.54 r180 top value=0.1uF
C32 "GRM155R71E104KE14D" 0402 54,-210 r90 bottom value=0.1uF
C33 "GRM155R71E104KE14D" 0402 385,-150 r90 bottom value=0.1uF
C34 "GRM155R71E104KE14D" 0402 51.38,-315 r180 top value=0.1uF
C35 "GRM155R71E104KE14D" 0402 256.02,-309.82 r180 top value=0.1uF
C36 "GRM155R71E104KE14D" 0402 565,-150 r90 bottom value=0.1uF
C37 "GRM155R71E104KE14D" 0402 744.84,-255.84 r0 top value=0.1uF
C41 "GRM155R71E104KE14D" 0402 2880,450 r90 bottom value=0.1uF
C42 "GRM155R61E105KE11D" 0402 2829.4,449.72 r90 bottom value=1uF
C43 "GJM1555C1H4R7BB01D" 0402 2627.38,415 r180 bottom value=4.7pF
C44 "GJM1555C1H4R7BB01D" 0402 2627.38,476 r180 bottom value=4.7pF
C45 "GJM1555C1H4R7BB01D" 0402 2658,305.8 r180 bottom value=4.7pF
C46 "GJM1555C1H4R7BB01D" 0402 2658,357.5 r180 bottom value=4.7pF
C47 "GRM155R61E225ME15D" 0402 2593.16,205.37 r0 bottom value=2.2uF
C48 "GRM155R71E104KE14D" 0402 2593.16,261.89 r0 bottom value=0.1uF
C49 "GRM155R71E104KE14D" 0402 2880.36,342.6 r270 bottom value=0.1uF
C50 "GRM155R61E105KE11D" 0402 2830.36,342.6 r270 bottom value=1uF
C59 "GRM2195C1H103JA01D" 0805_HV 3456,376 r180 bottom value=0.01uF
C60 "GRM155R71E104KE14D" 0402 1638.59,1339.03 r0 bottom value=0.1uF
C61 "GRM155R71E104KE14D" 0402 1381.18,1109.81 r180 bottom value=0.1uF
C62 "885012006060" 0603 -5,-226.81 r270 bottom value=330pF
C63 "885012006060" 0603 190,-148.5 r270 bottom value=330pF
C64 "885012006060" 0603 328.7,-161.5 r270 bottom value=330pF
C65 "885012006060" 0603 170.55,480.75 r270 top value=330pF
C66 "885012006060" 0603 305.37,480.75 r270 top value=330pF
C67 "885012006060" 0603 440.25,480.75 r270 top value=330pF
C68 "885012006060" 0603 510,-151.34 r270 bottom value=330pF
C69 "885012006060" 0603 698.19,-151.5 r270 bottom value=330pF
C70 "885012006060" 0603 841.45,-142.1 r270 bottom value=330pF
C71 "885012006060" 0603 575.14,480.75 r270 top value=330pF
C72 "885012006060" 0603 710.02,480.75 r270 top value=330pF
C73 "885012006060" 0603 844.9,480.75 r270 top value=330pF
C74 "885012006060" 0603 777.46,480.75 r270 top value=330pF
C75 "885012006060" 0603 -66.15,-226.81 r270 bottom value=330pF
C76 "885012006060" 0603 128.85,-148.5 r270 bottom value=330pF
C77 "885012006060" 0603 267.55,-161.5 r270 bottom value=330pF
C78 "885012006060" 0603 103.59,480.75 r270 top value=330pF
C79 "885012006060" 0603 237.93,480.75 r270 top value=330pF
C80 "885012006060" 0603 372.81,480.75 r270 top value=330pF
C81 "885012006060" 0603 448.85,-151.34 r270 bottom value=330pF
C82 "885012006060" 0603 637.04,-151.5 r270 bottom value=330pF
C83 "885012006060" 0603 780.3,-142.1 r270 bottom value=330pF
C84 "885012006060" 0603 507.7,480.75 r270 top value=330pF
C85 "885012006060" 0603 642.58,480.75 r270 top value=330pF
D1 "APHHS1005SURCK" APHHS1005_Red 2464.72,995 r180 top value=Red
D2 "APHHS1005CGCK" APHHS1005_Green 2464.72,945 r180 top value=Green
EC1 "controlCARD-120HSEC_Edge" controlCARD-120HSEC_Edge 901.05,-622.81 r0 top
EC2 "controlCARD-180HSEC-60pinAddon_Edge" controlCARD-180HSEC-60pinAddon_Edge 3237.32,-617.46 r0 top
FID1 "Fiducial" Fiducial10-20 -240,1925 r90 top
FID2 "Fiducial" Fiducial10-20 -240,-20 r90 top
FID3 "Fiducial" Fiducial10-20 3720,-300 r90 top
FID4 "Fiducial" Fiducial10-20 -240,1925 r90 bottom
FID5 "Fiducial" Fiducial10-20 -240,-20 r90 bottom
FID6 "Fiducial" Fiducial10-20 3720,-300 r90 bottom
J1 "QTH-060-01-L-D-A" SAMTEC_QTH-060-01-L-D-A 985,140 r180 top locked
J2 "QTH-060-01-L-D-A" SAMTEC_QTH-060-01-L-D-A -100,955 r270 top locked
J3 "QTH-060-01-L-D-A" SAMTEC_QTH-060-01-L-D-A 2065,955 r90 top locked
J4 "QTH-060-01-L-D-A" SAMTEC_QTH-060-01-L-D-A 985,1765 r180 top locked
J5 "7498010210A" Wurth_7498010210A 3627.37,1311.43 r0 top locked
J7 "TSW-108-08-G-D-RA-008" FP-TSW-108-08-G-D-RA-008_HDR15-MFG 3232.94,2018.43 r0 top
J8 "TMM-105-01-T-D" FP-TMM-105-01-T-D_HDR10-MFG 2540.71,1870 r180 bottom locked
J11 "7498010210A" Wurth_7498010210A 3627.37,358.15 r0 top locked
Logo1 "CE Mark" CE_Mark_5mm 1205,245 r180 bottom
Logo2 "Texas Instruments" TI_Stacked_Overlay_Small 1175,1865 r180 bottom
Logo3 "FCC disclaimer" FCC_disclaimer -3106.89,-2360 r270 bottom
Logo4 "WEEE logo" WEEE_Minimum 1180,-60 r180 bottom
MH1 "MTG_NoPads" MTG_159mil 1760,435 r0 top locked
MH2 "MTG_NoPads" MTG_159mil 0,1905 r0 top locked
MH3 "MTG_NoPads" MTG_159mil 1970,1905 r0 top locked
MH4 "MTG_NoPads" MTG_159mil 0,0 r0 top locked
R1 "CRG0402F4K7" 0402 2528.34,1109.63 r270 top value=4.70k
R2 "CRG0402F4K7" 0402 2327.18,1346.9 r270 bottom value=4.70k
R3 "CRCW04022K20FKED" 0402 2528.47,1571.25 r90 top value=2.20k
R4 "CRCW04026K49FKED" 0402 2560,1480 r180 top value=6.49k
R5 "CRCW04020000Z0EDHP" FP-CRCW04020000Z0EDHP_0402-MFG 2198.78,1249.88 r180 bottom value=0
R6 "CRCW04022K49FKED" 0402 2067.56,1350.43 r180 bottom value=2.49k
R7 "CRCW04022K49FKED" 0402 2468.47,1683.5 r90 top value=2.49k
R8 "CRCW04022K49FKED" 0402 2408.47,1683.5 r90 top value=2.49k
R9 "CRCW040233R2FKED" 0402 2189.79,1418.51 r0 bottom value=33.2
R10 "CRCW04020000Z0EDHP" FP-CRCW04020000Z0EDHP_0402-MFG 2320.94,1123.07 r270 top value=0
R11 "CRCW04020000Z0EDHP" FP-CRCW04020000Z0EDHP_0402-MFG 2277.16,1182.57 r180 top value=0
R12 "CRCW04020000Z0EDHP" FP-CRCW04020000Z0EDHP_0402-MFG 2299.35,1202.13 r180 bottom value=0
R13 "CRCW040233R2FKED" 0402 2191.85,1468.23 r0 bottom value=33.2
R14 "CRCW04020000Z0EDHP" FP-CRCW04020000Z0EDHP_0402-MFG 2320.08,1257.97 r180 bottom value=0
R15 "CRCW040233R2FKED" 0402 2348.47,1571.25 r270 top value=33.2
R16 "CRCW040233R2FKED" 0402 2408.47,1571.25 r270 top value=33.2
R17 "CRCW040233R2FKED" 0402 2468.47,1571.25 r270 top value=33.2
R18 "CRCW040233R2FKED" 0402 2175.08,1354.96 r0 bottom value=33.2
R19 "CRCW04022K20FKED" 0402 2480.52,1109.63 r270 top value=2.20k
R20 "CRCW040233R2FKED" 0402 2174.18,1301.83 r0 bottom value=33.2
R21 "ERJ-3GEY0R00V" 0603 2399.11,1494.03 r90 bottom value=0
R22 "ERJ-3GEY0R00V" 0603 2583.24,1109.01 r90 top value=0
R23 "CRCW04020000Z0EDHP" FP-CRCW04020000Z0EDHP_0402-MFG 2654.06,1451.12 r180 top value=0
R24 "CRCW040233R2FKED" 0402 2288.47,1571.25 r270 top value=33.2
R25 "CRCW0603470RJNEA" 0603 2967.76,1156.49 r270 bottom value=470
R26 "CRCW04022K20FKED" 0402 2369.79,1109.63 r90 top value=2.20k
R27 "CRCW04022K20FKED" 0402 2426.8,1109.63 r90 top value=2.20k
R28 "CRCW04022K49FKED" 0402 2051.41,1301.32 r0 bottom value=2.49k
R29 "CRCW04022K49FKED" 0402 2348.47,1683.5 r270 top value=2.49k
R30 "CRCW04022K49FKED" 0402 2066.93,1448 r0 bottom value=2.49k
R31 "CRCW04022K49FKED" 0402 2288.47,1683.5 r270 top value=2.49k
R32 "CRCW04020000Z0EDHP" FP-CRCW04020000Z0EDHP_0402-MFG 2645,545 r270 top value=0
R33 "CRCW04022K49FKED" 0402 2877.52,1538.79 r90 bottom value=2.49k
R34 "ERJ-6GEYJ105V" 0805_HV 3456,922 r0 bottom value=1.0Meg
R35 "ERJ-3GEY0R00V" 0603 2455,865 r0 top value=0
R36 "AC0402FR-0710KL" 0402 1389,381 r0 top value=10.0k
R38 "CRCW0603470RJNEA" 0603 2995,1494.5 r270 bottom value=470
R45 "CRG0402F4K7" 0402 -68.62,-309.39 r0 top value=4.70k
R46 "CRG0402F4K7" 0402 -68.62,-309.39 r0 bottom value=4.70k
R54 "ERJ-3GEY0R00V" 0603 2323.65,636.68 r0 bottom value=0
R55 "ERJ-3GEY0R00V" 0603 2584.4,139.85 r90 top value=0
R56 "CRG0402F4K7" 0402 2528.34,156.35 r270 top value=4.70k
R57 "CRG0402F4K7" 0402 2326.96,393.4 r270 bottom value=4.70k
R58 "CRCW04022K20FKED" 0402 2528.47,617.97 r90 top value=2.20k
R59 "CRCW04026K49FKED" 0402 2560,526.72 r180 top value=6.49k
R60 "CRCW04020000Z0EDHP" FP-CRCW04020000Z0EDHP_0402-MFG 2215.04,289.55 r180 bottom value=0
R61 "CRCW04022K49FKED" 0402 2122,445 r90 bottom value=2.49k
R62 "CRCW04022K49FKED" 0402 2468.47,730.22 r90 top value=2.49k
R63 "CRCW04022K49FKED" 0402 2408.47,730.22 r90 top value=2.49k
R64 "CRCW040233R2FKED" 0402 2209.53,410.68 r0 bottom value=33.2
R65 "CRCW04020000Z0EDHP" FP-CRCW04020000Z0EDHP_0402-MFG 2320.94,169.79 r270 top value=0
R66 "CRCW04020000Z0EDHP" FP-CRCW04020000Z0EDHP_0402-MFG 2286.32,169.71 r270 top value=0
R67 "CRCW04020000Z0EDHP" FP-CRCW04020000Z0EDHP_0402-MFG 2323.1,212.76 r270 bottom value=0
R68 "CRCW040233R2FKED" 0402 2196.86,485.04 r0 bottom value=33.2
R69 "CRCW04020000Z0EDHP" FP-CRCW04020000Z0EDHP_0402-MFG 2340.67,300 r0 bottom value=0
R70 "CRCW040233R2FKED" 0402 2348.47,617.97 r270 top value=33.2
R71 "CRCW040233R2FKED" 0402 2408.47,617.97 r270 top value=33.2
R72 "CRCW040233R2FKED" 0402 2468.47,617.97 r270 top value=33.2
R73 "CRCW040233R2FKED" 0402 2209.53,361.72 r0 bottom value=33.2
R74 "CRCW040233R2FKED" 0402 2092.23,352.87 r0 bottom value=33.2
R78 "CRCW040233R2FKED" 0402 2288.47,617.97 r270 top value=33.2
R79 "CRCW0603470RJNEA" 0603 2844.7,123.47 r180 bottom value=470
R80 "CRCW04022K20FKED" 0402 2369.79,156.35 r90 top value=2.20k
R81 "CRCW04022K20FKED" 0402 2426.8,156.35 r90 top value=2.20k
R82 "CRCW04022K20FKED" 0402 2480.52,156.35 r90 top value=2.20k
R83 "CRCW04022K49FKED" 0402 2060,445 r270 bottom value=2.49k
R84 "CRCW04022K49FKED" 0402 2348.47,730.22 r270 top value=2.49k
R85 "CRCW04022K49FKED" 0402 2197.3,534.38 r180 bottom value=2.49k
R86 "CRCW04022K49FKED" 0402 2288.47,730.22 r270 top value=2.49k
R87 "CRCW0603470RJNEA" 0603 2783.43,570.02 r180 bottom value=470
R88 "CRCW04022K49FKED" 0402 2794.69,663.27 r180 bottom value=2.49k
R89 "ERJ-6GEYJ105V" 0805_HV 3456,463 r0 bottom value=1.0Meg
R90 "CRCW04021K20JNED" 0402 2557.87,995 r180 top value=1.2k
R91 "CRG0402F4K7" 0402 1638.59,1440.03 r0 bottom value=4.70k
R92 "CRG0402F4K7" 0402 1638.59,1490.03 r0 bottom value=4.70k
R93 "CRCW04021K20JNED" 0402 2559.83,945 r180 top value=1.2k
R94 "CRCW04021M50JNED" 0402 1653.58,1147.21 r0 bottom value=1.5Meg
R95 "CRCW04021M50JNED" 0402 1653.58,1072.4 r0 bottom value=1.5Meg
R96 "CRCW04020000Z0ED" 0402 1638.59,1389.03 r0 bottom value=0
R97 "CRCW04020000Z0ED" 0402 -66.15,-215 r90 top value=0
R98 "CRCW04020000Z0ED" 0402 -5,-215 r90 top value=0
R99 "CRCW04020000Z0ED" 0402 128.85,-136.69 r90 top value=0
R100 "CRCW04020000Z0ED" 0402 190,-136.69 r90 top value=0
R101 "CRCW04020000Z0ED" 0402 267.55,-149.68 r90 top value=0
R102 "CRCW04020000Z0ED" 0402 328.7,-149.68 r90 top value=0
R103 "CRCW04020000Z0ED" 0402 103.59,492.56 r90 bottom value=0
R104 "CRCW04020000Z0ED" 0402 170.55,492.56 r90 bottom value=0
R105 "CRCW04020000Z0ED" 0402 237.93,492.56 r90 bottom value=0
R106 "CRCW04020000Z0ED" 0402 305.37,492.56 r90 bottom value=0
R107 "CRCW04020000Z0ED" 0402 370,490.32 r90 bottom value=0
R108 "CRCW04020000Z0ED" 0402 440,490.32 r90 bottom value=0
R109 "CRCW04020000Z0ED" 0402 448.85,-139.53 r90 top value=0
R110 "CRCW04020000Z0ED" 0402 510,-139.53 r90 top value=0
R111 "CRCW04020000Z0ED" 0402 637.04,-139.68 r90 top value=0
R112 "CRCW04020000Z0ED" 0402 698.19,-139.68 r90 top value=0
R113 "CRCW04020000Z0ED" 0402 780.3,-130.29 r90 top value=0
R114 "CRCW04020000Z0ED" 0402 841.45,-130.29 r90 top value=0
R115 "CRCW04020000Z0ED" 0402 507.7,492.56 r90 bottom value=0
R116 "CRCW04020000Z0ED" 0402 575.14,492.56 r90 bottom value=0
R117 "CRCW04020000Z0ED" 0402 642.58,491.57 r90 bottom value=0
R118 "CRCW04020000Z0ED" 0402 710.02,492.56 r90 bottom value=0
R119 "CRCW04020000Z0ED" 0402 777.46,491.57 r90 bottom value=0
R120 "CRCW04020000Z0ED" 0402 844.9,491.57 r90 bottom value=0
TP1 "CMP-0078143-4" TESTPOINT 2030,20 r0 top
TP2 "CMP-0078143-4" TESTPOINT 2010,-170 r90 top
TP3 "CMP-0078143-4" TESTPOINT 1770,-80 r0 top
TP4 "CMP-0078143-4" TESTPOINT 3125,865 r0 top
U1 "DP83826IRHBR" RHB0032M-MFG 2416.96,1332.32 r180 top
U2 "TPD4E05U06DQAR" DQA0010A 2643.73,1352 r0 top
U3 "DP83826IRHBR" RHB0032M-MFG 2416.96,379.04 r180 top
U4 "TPD4E001DPKR" DPK0006A 143.27,-290.88 r90 top
U5 "TPD4E001DPKR" DPK0006A 365,-290 r90 top
U6 "TPD4E05U06DQAR" DQA0010A 2643.73,398.72 r0 top
U7 "SN74LVC2G06DBVR" DBV0006A_N 1518.93,1109.81 r180 bottom
U8 "CAT24C16WI-GT3" SOIC-8 1406.59,1414.03 r0 bottom
U9 "TPD4E001DPKR" DPK0006A 599.35,-293.13 r90 top locked
U10 "TPD4E001DPKR" DPK0006A 143.27,-290.88 r270 bottom
U11 "TPD4E001DPKR" DPK0006A 365,-290 r270 bottom
U12 "TPD4E001DPKR" DPK0006A 599.35,-293.13 r270 bottom
ZZ1 "This Assembly Note is for PCB labels only" AssemblyNoteLabel -778.06,3336.69 r0 top
ZZ2 "These assemblies are ESD sensitive, ESD precautions shall be observed." AssemblyNote -778.06,3227.81 r0 top
ZZ3 "These assemblies must be clean and free from flux and all contaminants. Use of no clean flux is not acceptable." AssemblyNote -778.06,3139.25 r0 top
ZZ4 "These assemblies must comply with workmanship standards IPC-A-610 Class 2, unless otherwise specified." AssemblyNote -778.06,3050.69 r0 top

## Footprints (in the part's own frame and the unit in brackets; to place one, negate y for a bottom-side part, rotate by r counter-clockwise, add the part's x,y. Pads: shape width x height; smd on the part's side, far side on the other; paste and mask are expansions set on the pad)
0402 [mm] "0402 from SM-752 data"
  rect 0.8x0.6 smd: 1(-0.6,0) 2(0.6,0)
  silkscreen extent -1.22,-0.52 1.22,0.52, body extent -0.55,-0.3 0.55,0.3, height 0.6
0603 [mm] "0603 from SM-752 data"
  rect 1x0.95 smd: 1(-0.8,0) 2(0.8,0)
  silkscreen extent -1.52,-0.69 1.52,0.69, body extent -0.87,-0.47 0.87,0.47, height 1
0805_HV [mil] "0805 with 30mil clearance between pads"
  rect 50x63 smd: 1(-40,0) 2(40,0)
  silkscreen extent -74,-40 74,40, body extent -43,-29 43,29, height 57
APHHS1005_Green [mm] "SMD, 2-Leads, Body 1x0.5mm"
  rrect20% 0.7x0.5 smd: 1(-0.45,0) 2(0.45,0)
  silkscreen extent -0.8,-0.65 1.2,0.65, body extent -0.5,-0.25 0.5,0.25, height 0.5
APHHS1005_Red [mm] "SMD, 2-Leads, Body 1x0.5mm"
  rrect20% 0.7x0.5 smd: 1(-0.45,0) 2(0.45,0)
  silkscreen extent -0.8,-0.65 1.2,0.65, body extent -0.5,-0.25 0.5,0.25, height 0.5
AssemblyNote [mil] "Assembly Note"
AssemblyNoteLabel [mil] "Assembly Note for PCB Labels"
CE_Mark_5mm [mil] "Minimum text height for CE Mark"
  silkscreen extent -138,-98 138,98
controlCARD-120HSEC_Edge [mm] "Edge Connector, 0.8mm, 60x2, pad numbers do not match Samtec datasheet"
  rect 0.55x2.8 smd paste-2.5 mask+0: 1(-23.6,2.4) 3(-22.8,2.4) 5(-22,2.4) 7(-21.2,2.4) 9(-20.4,2.4) 11(-19.6,2.4) 13(-18.8,2.4) 15(-18,2.4) 17(-17.2,2.4) 19(-16.4,2.4) 21(-15.6,2.4) 23(-14.8,2.4) 25(-14,2.4) 27(-13.2,2.4) 29(-12.4,2.4) 31(-11.6,2.4) 33(-10.8,2.4) 35(-10,2.4) 37(-9.2,2.4) 39(-8.4,2.4) 41(-7.6,2.4) 43(-6.8,2.4) 45(-6,2.4) 47(-5.2,2.4) 49(-4.4,2.4) 51(-3.6,2.4) 53(-2.8,2.4) 55(-2,2.4) 57(2,2.4) 59(2.8,2.4) 61(3.6,2.4) 63(4.4,2.4) 65(5.2,2.4) 67(6,2.4) 69(6.8,2.4) 71(7.6,2.4) 73(8.4,2.4) 75(9.2,2.4) 77(10,2.4) 79(10.8,2.4) 81(11.6,2.4) 83(12.4,2.4) 85(13.2,2.4) 87(14,2.4) 89(14.8,2.4) 91(15.6,2.4) 93(16.4,2.4) 95(17.2,2.4) 97(18,2.4) 99(18.8,2.4) 101(19.6,2.4) 103(20.4,2.4) 105(21.2,2.4) 107(22,2.4) 109(22.8,2.4) 111(23.6,2.4) 113(24.4,2.4) 115(25.2,2.4) 117(26,2.4) 119(26.8,2.4)
  rect 0.55x2.8 smd far side paste-2.5 mask+0: 2(-23.6,2.4) 4(-22.8,2.4) 6(-22,2.4) 8(-21.2,2.4) 10(-20.4,2.4) 12(-19.6,2.4) 14(-18.8,2.4) 16(-18,2.4) 18(-17.2,2.4) 20(-16.4,2.4) 22(-15.6,2.4) 24(-14.8,2.4) 26(-14,2.4) 28(-13.2,2.4) 30(-12.4,2.4) 32(-11.6,2.4) 34(-10.8,2.4) 36(-10,2.4) 38(-9.2,2.4) 40(-8.4,2.4) 42(-7.6,2.4) 44(-6.8,2.4) 46(-6,2.4) 48(-5.2,2.4) 50(-4.4,2.4) 52(-3.6,2.4) 54(-2.8,2.4) 56(-2,2.4) 58(2,2.4) 60(2.8,2.4) 62(3.6,2.4) 64(4.4,2.4) 66(5.2,2.4) 68(6,2.4) 70(6.8,2.4) 72(7.6,2.4) 74(8.4,2.4) 76(9.2,2.4) 78(10,2.4) 80(10.8,2.4) 82(11.6,2.4) 84(12.4,2.4) 86(13.2,2.4) 88(14,2.4) 90(14.8,2.4) 92(15.6,2.4) 94(16.4,2.4) 96(17.2,2.4) 98(18,2.4) 100(18.8,2.4) 102(19.6,2.4) 104(20.4,2.4) 106(21.2,2.4) 108(22,2.4) 110(22.8,2.4) 112(23.6,2.4) 114(24.4,2.4) 116(25.2,2.4) 118(26,2.4) 120(26.8,2.4)
controlCARD-180HSEC-60pinAddon_Edge [mm] "Edge Connector, 0.8mm, 30x2, pad numbers do not match Samtec datasheet"
  rect 0.55x2.8 smd paste-2.5 mask+0: 121(-11.6,2.4) 123(-10.8,2.4) 125(-10,2.4) 127(-9.2,2.4) 129(-8.4,2.4) 131(-7.6,2.4) 133(-6.8,2.4) 135(-6,2.4) 137(-5.2,2.4) 139(-4.4,2.4) 141(-3.6,2.4) 143(-2.8,2.4) 145(-2,2.4) 147(-1.2,2.4) 149(-0.4,2.4) 151(0.4,2.4) 153(1.2,2.4) 155(2,2.4) 157(2.8,2.4) 159(3.6,2.4) 161(4.4,2.4) 163(5.2,2.4) 165(6,2.4) 167(6.8,2.4) 169(7.6,2.4) 171(8.4,2.4) 173(9.2,2.4) 175(10,2.4) 177(10.8,2.4) 179(11.6,2.4)
  rect 0.55x2.8 smd far side paste-2.5 mask+0: 122(-11.6,2.4) 124(-10.8,2.4) 126(-10,2.4) 128(-9.2,2.4) 130(-8.4,2.4) 132(-7.6,2.4) 134(-6.8,2.4) 136(-6,2.4) 138(-5.2,2.4) 140(-4.4,2.4) 142(-3.6,2.4) 144(-2.8,2.4) 146(-2,2.4) 148(-1.2,2.4) 150(-0.4,2.4) 152(0.4,2.4) 154(1.2,2.4) 156(2,2.4) 158(2.8,2.4) 160(3.6,2.4) 162(4.4,2.4) 164(5.2,2.4) 166(6,2.4) 168(6.8,2.4) 170(7.6,2.4) 172(8.4,2.4) 174(9.2,2.4) 176(10,2.4) 178(10.8,2.4) 180(11.6,2.4)
DBV0006A_N [mm] "SOT23, 6-Leads, Body 2.9x1.6mm, Pitch 0.95mm, Lead Span 2.8mm, IPC Medium Density"
  rrect17% 1x0.6 smd: 1(-1.375,0.95) 2(-1.375,0) 3(-1.375,-0.95) 4(1.375,-0.95) 5(1.375,0) 6(1.375,0.95)
  silkscreen extent -1.68,-1.55 0.5,1.55, body extent -1.42,-1.46 1.42,1.46, height 1.12
DPK0006A [mm] "SON, 6-Leads, Body 1.6x1.6mm, Pitch 0.5mm, TI Recommended"
  rect 0.5x0.2 smd paste+0: 1(-0.75,0.5) 2(-0.75,0) 3(-0.75,-0.5) 4(0.75,-0.5) 5(0.75,0) 6(0.75,0.5)
  Top Layer region: -0.65,0.5 -0.5,0.5 -0.5,0.7 -0.65,0.7
  silkscreen extent -0.97,-1 0.85,1, body extent -0.85,-0.85 0.85,0.85, height 0.61
DQA0010A [mm] "SON, 10-Leads, Body 1x2.5mm, Pitch 0.5mm, TI Recommended"
  rrect50% 0.565x0.2 smd: 1(-0.417,1) 2(-0.417,0.5) 4(-0.417,-0.5) 5(-0.417,-1) 6(0.417,-1) 7(0.417,-0.5) 9(0.417,0.5) 10(0.417,1)
  rrect28% 0.565x0.36 on Top Paste: 3(-0.417,0) 8(0.417,0)
  rrect25% 0.565x0.4 smd paste-0.2: 3(-0.417,0) 8(0.417,0)
  silkscreen extent -0.67,-1.45 0.55,1.45, body extent -0.55,-1.3 0.55,1.3, height 0.56
FCC_disclaimer [mil]
Fiducial10-20 [mm]
  round 1 smd mask+0.5: 1(0,0)
  Top Layer keep-out circle w1.178: c0,0 r0.5
FP-CRCW04020000Z0EDHP_0402-MFG [mm]
  rrect17% 0.6x0.6 smd paste+0 mask+0: 1(-0.525,0) 2(0.525,0)
  silkscreen extent -0.53,-0.7 0.53,0.7, body extent -0.5,-0.25 0.5,0.25, height 0.4
FP-GRM188R60J476ME01D_0603-MFG [mm]
  rrect13% 0.75x0.9 smd paste+0 mask+0: 1(-0.775,0) 2(0.775,0)
  silkscreen extent -0.9,-0.9 0.9,0.9, body extent -0.8,-0.4 0.8,0.4, height 1
FP-TMM-105-01-T-D_HDR10-MFG [mm]
  rrect7% 1.39x1.39 hole 0.89 paste-2539.97 mask+0: 1(-4,-1)
  round 1.39 hole 0.89 paste-2539.97 mask+0: 2(-4,1) 3(-2,-1) 4(-2,1) 5(0,-1) 6(0,1) 7(2,-1) 8(2,1) 9(4,-1) 10(4,1)
  body extent -5,-1.97 5,1.97, height 4.88
FP-TSW-108-08-G-D-RA-008_HDR15-MFG [mm]
  rrect6% 1.57x1.57 hole 1.02 paste-2539.97 mask+0: 1(8.89,-2.77)
  round 1.57 hole 1.02 paste-2539.97 mask+0: 2(8.89,-5.31) 3(6.35,-2.77) 4(6.35,-5.31) 5(3.81,-2.77) 6(3.81,-5.31) 7(1.27,-2.77) 9(-1.27,-2.77) 10(-1.27,-5.31) 11(-3.81,-2.77) 12(-3.81,-5.31) 13(-6.35,-2.77) 14(-6.35,-5.31) 15(-8.89,-2.77) 16(-8.89,-5.31)
  silkscreen extent -10.35,-2.89 10.35,1.34, body extent -10.45,-6.14 10.45,7.52, height 0.25
MTG_159mil [mil] "159mil Non Plated Hole"
  round 150 hole 159 unplated: 1(0,0)
RHB0032M-MFG [mm]
  rrect40% 0.6x0.25 smd paste+0 mask+0: 1(-2.4,1.75) 2(-2.4,1.25) 3(-2.4,0.75) 4(-2.4,0.25) 5(-2.4,-0.25) 6(-2.4,-0.75) 7(-2.4,-1.25) 8(-2.4,-1.75) 17(2.4,-1.75) 18(2.4,-1.25) 19(2.4,-0.75) 20(2.4,-0.25) 21(2.4,0.25) 22(2.4,0.75) 23(2.4,1.25) 24(2.4,1.75)
  rrect40% 0.25x0.6 smd paste+0 mask+0: 9(-1.75,-2.4) 10(-1.25,-2.4) 11(-0.75,-2.4) 12(-0.25,-2.4) 13(0.25,-2.4) 14(0.75,-2.4) 15(1.25,-2.4) 16(1.75,-2.4) 25(1.75,2.4) 26(1.25,2.4) 27(0.75,2.4) 28(0.25,2.4) 29(-0.25,2.4) 30(-0.75,2.4) 31(-1.25,2.4) 32(-1.75,2.4)
  rrect5% 2.1x2.1 smd paste-1000 mask+0: 33(0,0)
  silkscreen extent -3.4,-2.55 2.55,2.55, body extent -2.8,-2.8 2.8,2.8, height 0.25
SAMTEC_QTH-060-01-L-D-A [mm] "SMD, 60x2 Position, Body 40.01x5.97mm"
  rect 0.305x1.45 smd: 1(-17.25,3.086) 2(-17.25,-3.086) 3(-16.75,3.086) 4(-16.75,-3.086) 5(-16.25,3.086) 6(-16.25,-3.086) 7(-15.75,3.086) 8(-15.75,-3.086) 9(-15.25,3.086) 10(-15.25,-3.086) 11(-14.75,3.086) 12(-14.75,-3.086) 13(-14.25,3.086) 14(-14.25,-3.086) 15(-13.75,3.086) 16(-13.75,-3.086) 17(-13.25,3.086) 18(-13.25,-3.086) 19(-12.75,3.086) 20(-12.75,-3.086) 21(-12.25,3.086) 22(-12.25,-3.086) 23(-11.75,3.086) 24(-11.75,-3.086) 25(-11.25,3.086) 26(-11.25,-3.086) 27(-10.75,3.086) 28(-10.75,-3.086) 29(-10.25,3.086) 30(-10.25,-3.086) 31(-9.75,3.086) 32(-9.75,-3.086) 33(-9.25,3.086) 34(-9.25,-3.086) 35(-8.75,3.086) 36(-8.75,-3.086) 37(-8.25,3.086) 38(-8.25,-3.086) 39(-7.75,3.086) 40(-7.75,-3.086) 41(-7.25,3.086) 42(-7.25,-3.086) 43(-6.75,3.086) 44(-6.75,-3.086) 45(-6.25,3.086) 46(-6.25,-3.086) 47(-5.75,3.086) 48(-5.75,-3.086) 49(-5.25,3.086) 50(-5.25,-3.086) 51(-4.75,3.086) 52(-4.75,-3.086) 53(-4.25,3.086) 54(-4.25,-3.086) 55(-3.75,3.086) 56(-3.75,-3.086) 57(-3.25,3.086) 58(-3.25,-3.086) 59(-2.75,3.086) 60(-2.75,-3.086) 61(2.75,3.086) 62(2.75,-3.086) 63(3.25,3.086) 64(3.25,-3.086) 65(3.75,3.086) 66(3.75,-3.086) 67(4.25,3.086) 68(4.25,-3.086) 69(4.75,3.086) 70(4.75,-3.086) 71(5.25,3.086) 72(5.25,-3.086) 73(5.75,3.086) 74(5.75,-3.086) 75(6.25,3.086) 76(6.25,-3.086) 77(6.75,3.086) 78(6.75,-3.086) 79(7.25,3.086) 80(7.25,-3.086) 81(7.75,3.086) 82(7.75,-3.086) 83(8.25,3.086) 84(8.25,-3.086) 85(8.75,3.086) 86(8.75,-3.086) 87(9.25,3.086) 88(9.25,-3.086) 89(9.75,3.086) 90(9.75,-3.086) 91(10.25,3.086) 92(10.25,-3.086) 93(10.75,3.086) 94(10.75,-3.086) 95(11.25,3.086) 96(11.25,-3.086) 97(11.75,3.086) 98(11.75,-3.086) 99(12.25,3.086) 100(12.25,-3.086) 101(12.75,3.086) 102(12.75,-3.086) 103(13.25,3.086) 104(13.25,-3.086) 105(13.75,3.086) 106(13.75,-3.086) 107(14.25,3.086) 108(14.25,-3.086) 109(14.75,3.086) 110(14.75,-3.086) 111(15.25,3.086) 112(15.25,-3.086) 113(15.75,3.086) 114(15.75,-3.086) 115(16.25,3.086) 116(16.25,-3.086) 117(16.75,3.086) 118(16.75,-3.086) 119(17.25,3.086) 120(17.25,-3.086)
  rect 2.54x0.64 smd: A1(-18.44,0) A4(-1.55,0) A5(1.56,0) A8(18.45,0)
  rect 4.7x0.64 smd: A2(-13.17,0) A3(-6.82,0) A6(6.83,0) A7(13.18,0)
  round 1.15 hole 1.15 unplated mask+0: MH1(-19.24,2.03) MH2(19.24,2.03)
  silkscreen extent -20,-2.99 20,2.99, body extent -20.07,-3.56 19.94,3.56, height 4.32
SOIC-8 [mm] "duplicate of SO-8.  SOIC, 8-Leads, Body 5.0x4.0mm (max), Pitch 1.27mm, IPC Medium Density"
  rrect17% 1.45x0.6 smd: 1(-2.725,1.905) 2(-2.725,0.635) 3(-2.725,-0.635) 4(-2.725,-1.905) 5(2.725,-1.905) 6(2.725,-0.635) 7(2.725,0.635) 8(2.725,1.905)
  silkscreen extent -3.5,-2.5 0.9,2.5, body extent -3,-2.45 3,2.45, height 1.63
TESTPOINT [mil]
  round 80 hole 37.99: 1(0,0)
  silkscreen extent -54,-53 54,53
TI_Stacked_Overlay_Small [mil]
  silkscreen extent -418,-98 418,98
WEEE_Minimum [mil] "WEEElie bin"
  silkscreen extent -95,-172 99,104
Wurth_7498010210A [mm] "Connector, RJ45, 1x1, Gold, R/A, SMT"
  rrect12% 4.6x0.81 smd: 1(-20.69,6.61) 2(-20.69,4.77) 11(-20.69,-4.77) 12(-20.69,-6.61)
  rrect16% 4.6x0.61 smd: 3(-20.69,3.57) 4(-20.69,2.55) 5(-20.69,1.53) 6(-20.69,0.51) 7(-20.69,-0.51) 8(-20.69,-1.53) 9(-20.69,-2.55) 10(-20.69,-3.57)
  rrect3% 4.9x3 smd: 13(0,8.92) 14(0,-8.92)
  round 2.5 hole 2.8 unplated mask+0.102: ALIGN1(0,6.35) ALIGN2(0,-6.35)
  body extent -21.42,-9.65 5.43,9.65, height 15.22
